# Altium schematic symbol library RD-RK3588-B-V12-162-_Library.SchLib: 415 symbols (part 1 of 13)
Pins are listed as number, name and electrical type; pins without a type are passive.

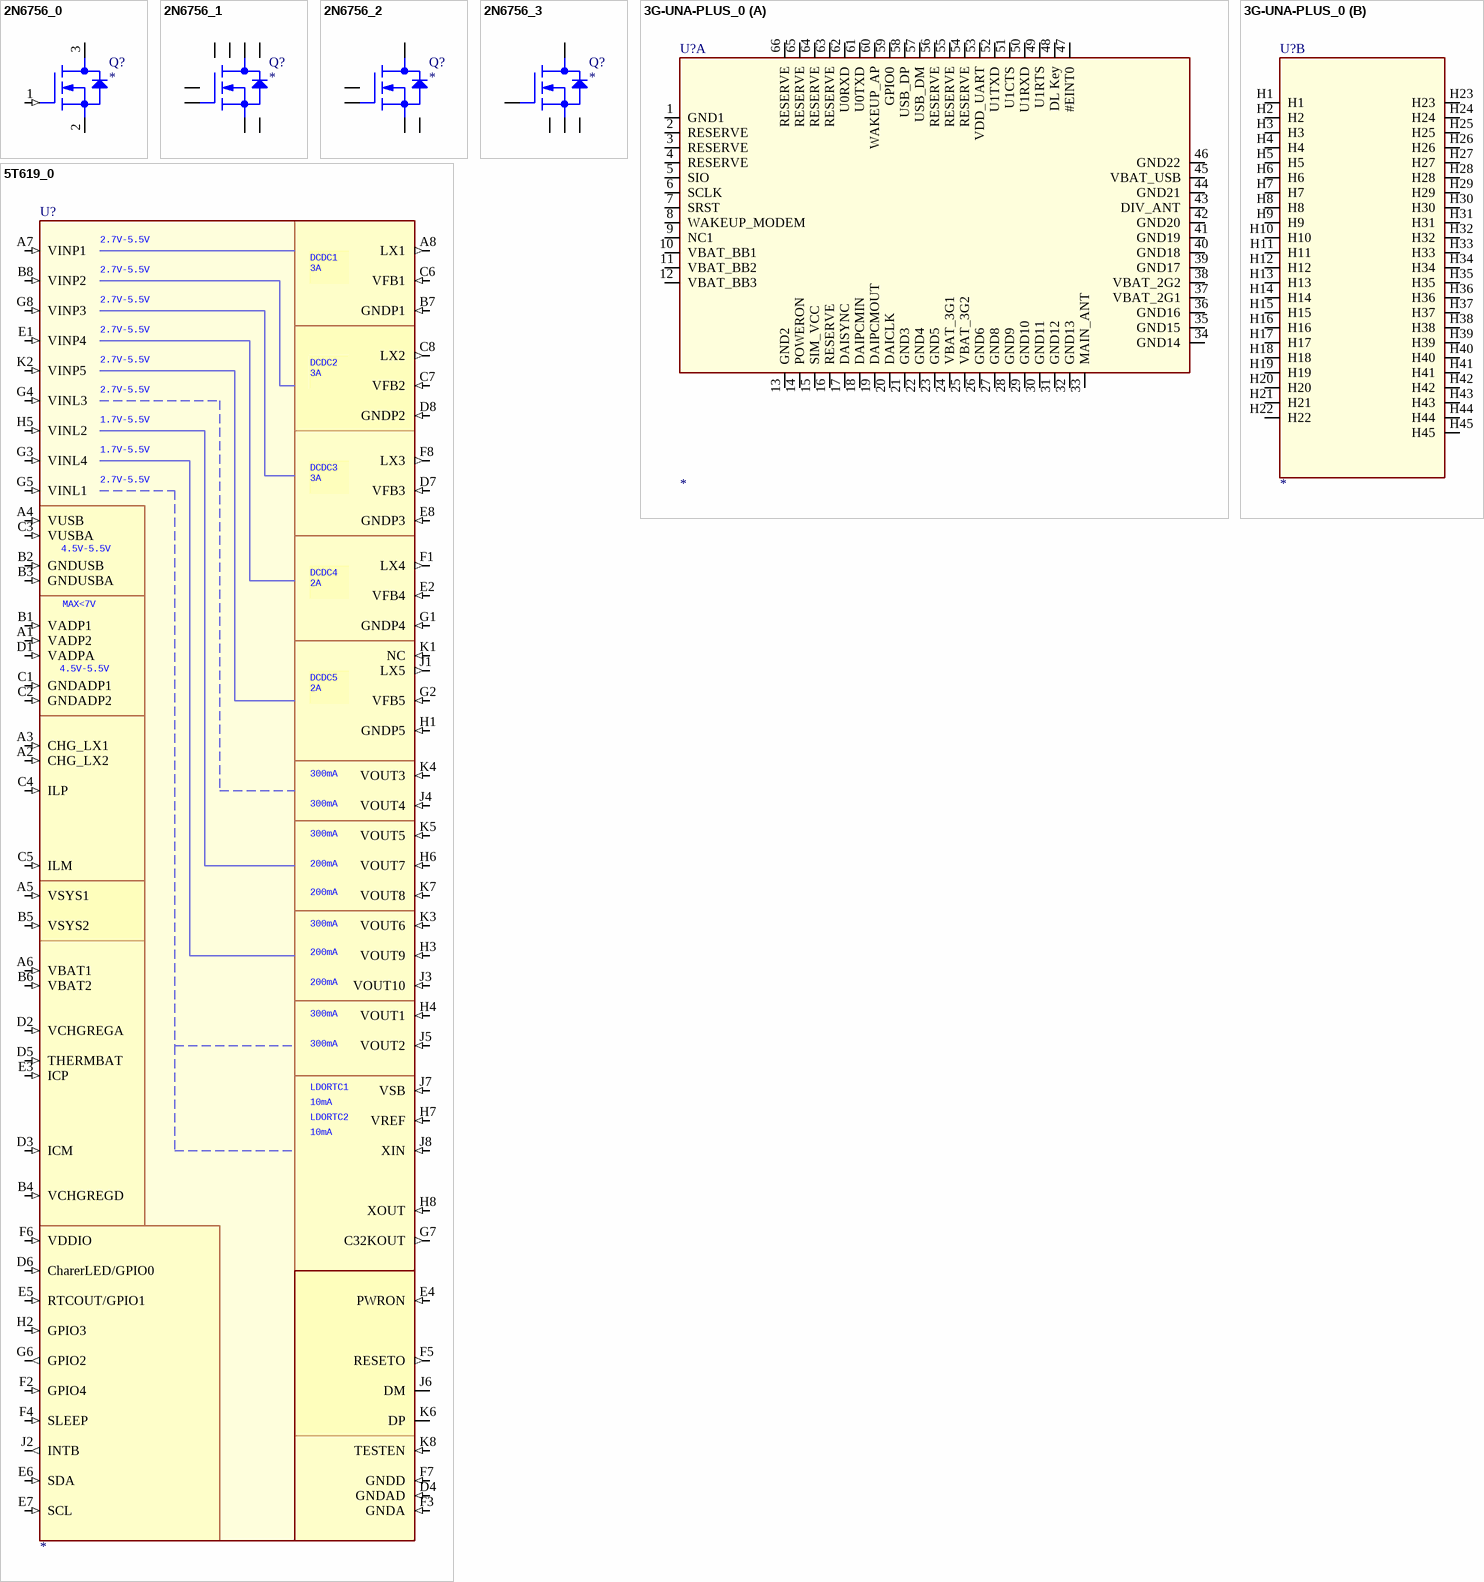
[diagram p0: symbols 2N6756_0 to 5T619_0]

## 2N6756_0
designator Q?
pins: 1 GATE (in), 2 SOURCE, 3 DRAIN

## 2N6756_1
designator Q?
pins: D1, D2, D3, D4, G1, G2, S1, S2

## 2N6756_2
designator Q?
pins: D1, G1, G2, S1, S2

## 2N6756_3
designator Q?
pins: D1, G1, G2, S1, S2

## 3G-UNA-PLUS_0
designator U?
part A pins: 1 GND1, 2 RESERVE, 3 RESERVE, 4 RESERVE, 5 SIO, 6 SCLK, 7 SRST, 8 WAKEUP_MODEM, 9 NC1, 10 VBAT_BB1, 11 VBAT_BB2, 12 VBAT_BB3, 13 GND2, 14 POWERON, 15 SIM_VCC, 16 RESERVE, 17 DAISYNC, 18 DAIPCMIN, 19 DAIPCMOUT, 20 DAICLK, 21 GND3, 22 GND4, 23 GND5, 24 VBAT_3G1, 25 VBAT_3G2, 26 GND6, 27 GND8, 28 GND9, 29 GND10, 30 GND11, 31 GND12, 32 GND13, 33 MAIN_ANT, 34 GND14, 35 GND15, 36 GND16, 37 VBAT_2G1, 38 VBAT_2G2, 39 GND17, 40 GND18, 41 GND19, 42 GND20, 43 DIV_ANT, 44 GND21, 45 VBAT_USB, 46 GND22, 47 #EINT0, 48 DL Key, 49 U1RTS, 50 U1RXD, 51 U1CTS, 52 U1TXD, 53 VDD_UART, 54 RESERVE, 55 RESERVE, 56 RESERVE, 57 USB_DM, 58 USB_DP, 59 GPIO0, 60 WAKEUP_AP, 61 U0TXD, 62 U0RXD, 63 RESERVE, 64 RESERVE, 65 RESERVE, 66 RESERVE
part B pins: H1, H2, H3, H4, H5, H6, H7, H8, H9, H10, H11, H12, H13, H14, H15, H16, H17, H18, H19, H20, H21, H22, H23, H24, H25, H26, H27, H28, H29, H30, H31, H32, H33, H34, H35, H36, H37, H38, H39, H40, H41, H42, H43, H44, H45

## 5T619_0
designator U?
pins: A1 VADP2 (in), A2 CHG_LX2 (in), A3 CHG_LX1 (in), A4 VUSB (in), A5 VSYS1 (in), A6 VBAT1 (in), A7 VINP1 (in), A8 LX1 (out), B1 VADP1 (in), B2 GNDUSB (in), B3 GNDUSBA (in), B4 VCHGREGD (in), B5 VSYS2 (in), B6 VBAT2 (in), B7 GNDP1 (in), B8 VINP2 (in), C1 GNDADP1 (in), C2 GNDADP2 (in), C3 VUSBA (in), C4 ILP (in), C5 ILM (in), C6 VFB1 (in), C7 VFB2 (in), C8 LX2 (out), D1 VADPA (in), D2 VCHGREGA (in), D3 ICM (in), D4 GNDAD (in), D5 THERMBAT (in), D6 CharerLED/GPIO0 (in), D7 VFB3 (in), D8 GNDP2 (in), E1 VINP4 (in), E2 VFB4 (in), E3 ICP (in), E4 PWRON (in), E5 RTCOUT/GPIO1 (in), E6 SDA (in), E7 SCL (in), E8 GNDP3 (in), F1 LX4 (out), F2 GPIO4 (in), F3 GNDA (in), F4 SLEEP (in), F5 RESETO (out), F6 VDDIO (in), F7 GNDD (in), F8 LX3 (out), G1 GNDP4 (in), G2 VFB5 (in), G3 VINL4 (in), G4 VINL3 (in), G5 VINL1 (in), G6 GPIO2 (out), G7 C32KOUT (out), G8 VINP3 (in), H1 GNDP5 (in), H2 GPIO3 (in), H3 VOUT9 (in), H4 VOUT1 (in), H5 VINL2 (in), H6 VOUT7 (in), H7 VREF (in), H8 XOUT (in), J1 LX5 (out), J2 INTB (out), J3 VOUT10 (in), J4 VOUT4 (in), J5 VOUT2 (in), J6 DM, J7 VSB (in), J8 XIN (in), K1 NC (in), K2 VINP5 (in), K3 VOUT6 (in), K4 VOUT3 (in), K5 VOUT5 (in), K6 DP, K7 VOUT8 (in), K8 TESTEN (in)

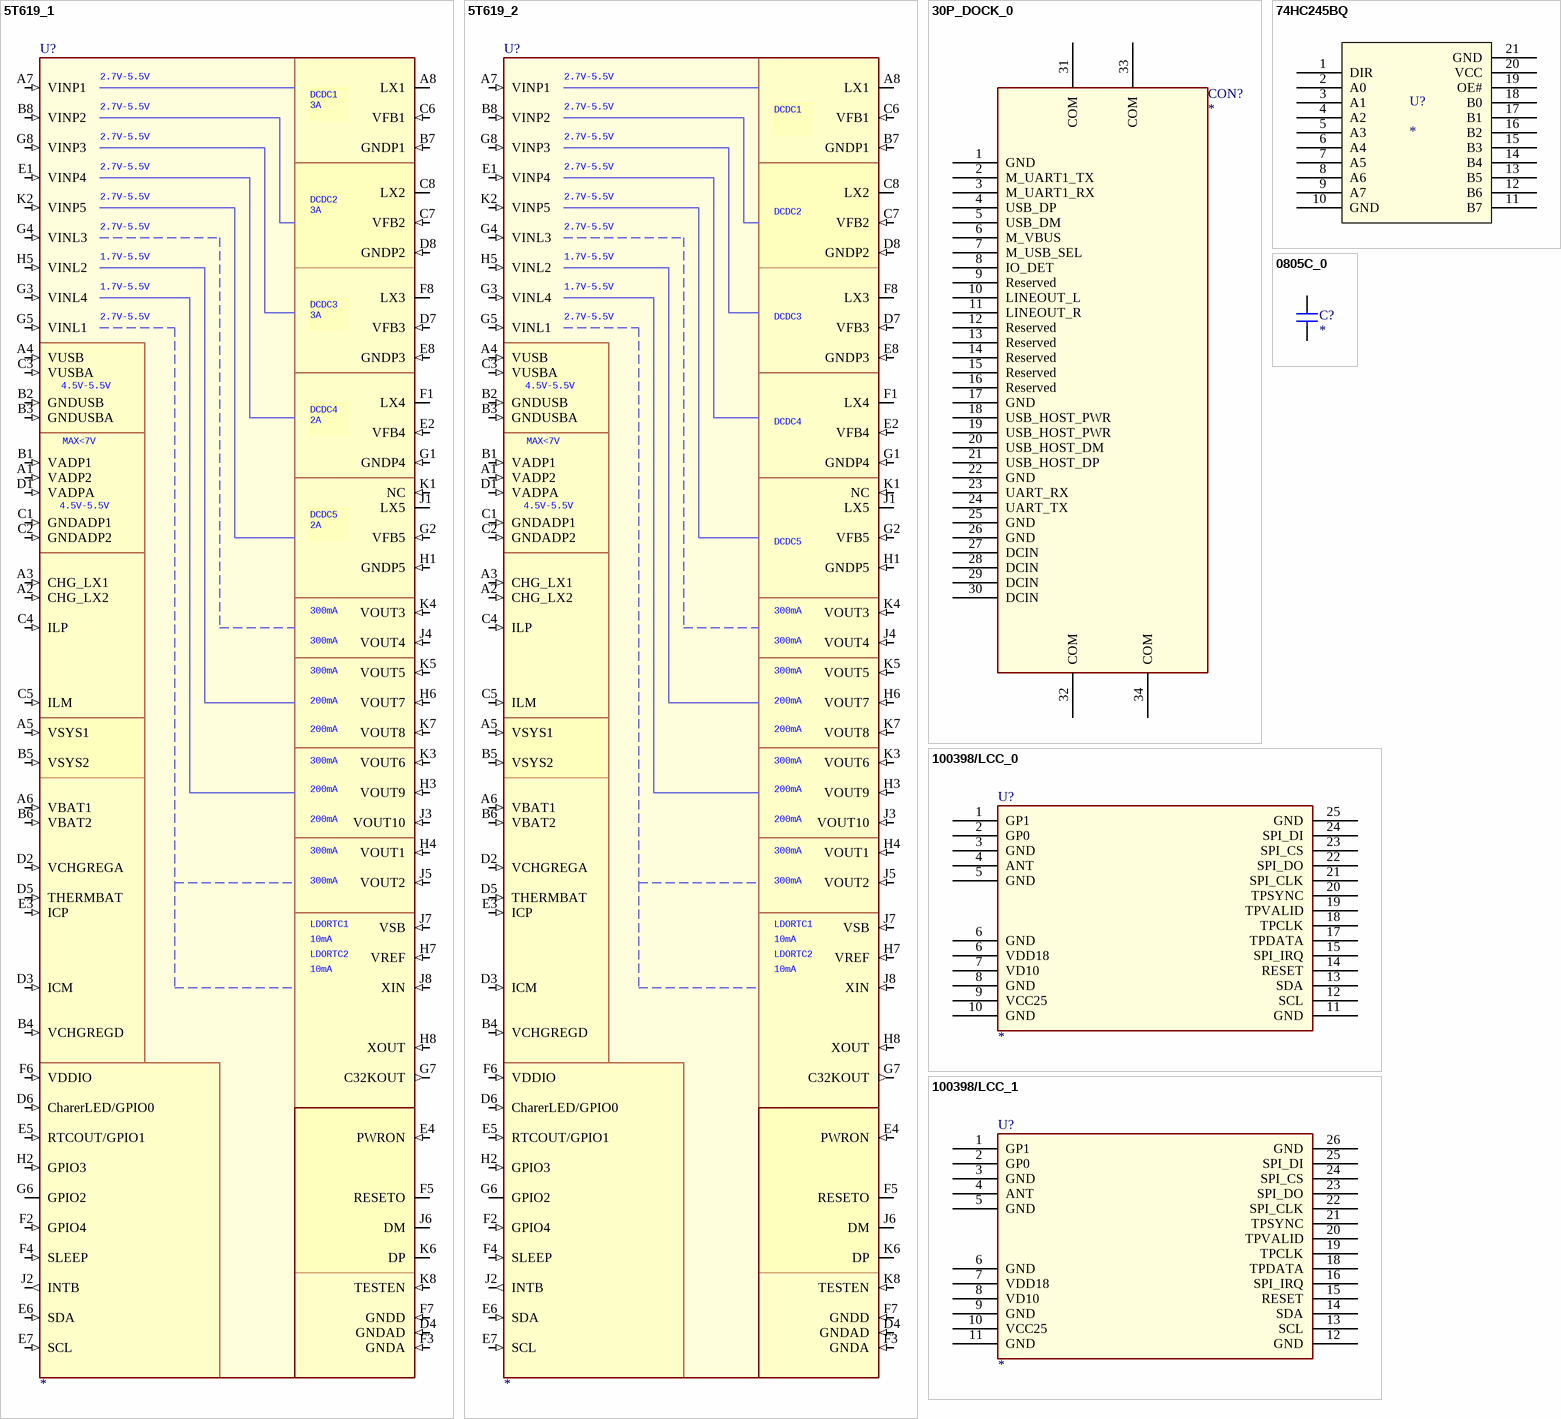
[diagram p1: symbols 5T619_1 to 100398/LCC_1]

## 5T619_1
designator U?
pins: A1 VADP2 (in), A2 CHG_LX2 (in), A3 CHG_LX1 (in), A4 VUSB (in), A5 VSYS1 (in), A6 VBAT1 (in), A7 VINP1 (in), A8 LX1, B1 VADP1 (in), B2 GNDUSB (in), B3 GNDUSBA (in), B4 VCHGREGD (in), B5 VSYS2 (in), B6 VBAT2 (in), B7 GNDP1 (in), B8 VINP2 (in), C1 GNDADP1 (in), C2 GNDADP2 (in), C3 VUSBA (in), C4 ILP (in), C5 ILM (in), C6 VFB1 (in), C7 VFB2 (in), C8 LX2, D1 VADPA (in), D2 VCHGREGA (in), D3 ICM (in), D4 GNDAD (in), D5 THERMBAT (in), D6 CharerLED/GPIO0 (in), D7 VFB3 (in), D8 GNDP2 (in), E1 VINP4 (in), E2 VFB4 (in), E3 ICP (in), E4 PWRON (in), E5 RTCOUT/GPIO1 (in), E6 SDA (in), E7 SCL (in), E8 GNDP3 (in), F1 LX4, F2 GPIO4 (in), F3 GNDA (in), F4 SLEEP (in), F5 RESETO, F6 VDDIO (in), F7 GNDD (in), F8 LX3, G1 GNDP4 (in), G2 VFB5 (in), G3 VINL4 (in), G4 VINL3 (in), G5 VINL1 (in), G6 GPIO2, G7 C32KOUT (out), G8 VINP3 (in), H1 GNDP5 (in), H2 GPIO3 (in), H3 VOUT9 (in), H4 VOUT1 (in), H5 VINL2 (in), H6 VOUT7 (in), H7 VREF (in), H8 XOUT (in), J1 LX5, J2 INTB (out), J3 VOUT10 (in), J4 VOUT4 (in), J5 VOUT2 (in), J6 DM, J7 VSB (in), J8 XIN (in), K1 NC (in), K2 VINP5 (in), K3 VOUT6 (in), K4 VOUT3 (in), K5 VOUT5 (in), K6 DP, K7 VOUT8 (in), K8 TESTEN (in)

## 5T619_2
designator U?
pins: A1 VADP2 (in), A2 CHG_LX2 (in), A3 CHG_LX1 (in), A4 VUSB (in), A5 VSYS1 (in), A6 VBAT1 (in), A7 VINP1 (in), A8 LX1, B1 VADP1 (in), B2 GNDUSB (in), B3 GNDUSBA (in), B4 VCHGREGD (in), B5 VSYS2 (in), B6 VBAT2 (in), B7 GNDP1 (in), B8 VINP2 (in), C1 GNDADP1 (in), C2 GNDADP2 (in), C3 VUSBA (in), C4 ILP (in), C5 ILM (in), C6 VFB1 (in), C7 VFB2 (in), C8 LX2, D1 VADPA (in), D2 VCHGREGA (in), D3 ICM (in), D4 GNDAD (in), D5 THERMBAT (in), D6 CharerLED/GPIO0 (in), D7 VFB3 (in), D8 GNDP2 (in), E1 VINP4 (in), E2 VFB4 (in), E3 ICP (in), E4 PWRON (in), E5 RTCOUT/GPIO1 (in), E6 SDA (in), E7 SCL (in), E8 GNDP3 (in), F1 LX4, F2 GPIO4 (in), F3 GNDA (in), F4 SLEEP (in), F5 RESETO, F6 VDDIO (in), F7 GNDD (in), F8 LX3, G1 GNDP4 (in), G2 VFB5 (in), G3 VINL4 (in), G4 VINL3 (in), G5 VINL1 (in), G6 GPIO2, G7 C32KOUT (out), G8 VINP3 (in), H1 GNDP5 (in), H2 GPIO3 (in), H3 VOUT9 (in), H4 VOUT1 (in), H5 VINL2 (in), H6 VOUT7 (in), H7 VREF (in), H8 XOUT (in), J1 LX5, J2 INTB (out), J3 VOUT10 (in), J4 VOUT4 (in), J5 VOUT2 (in), J6 DM, J7 VSB (in), J8 XIN (in), K1 NC (in), K2 VINP5 (in), K3 VOUT6 (in), K4 VOUT3 (in), K5 VOUT5 (in), K6 DP, K7 VOUT8 (in), K8 TESTEN (in)

## 30P_DOCK_0
designator CON?
footprint 30P_DOCK_1
pins: 1 GND, 2 M_UART1_TX, 3 M_UART1_RX, 4 USB_DP, 5 USB_DM, 6 M_VBUS, 7 M_USB_SEL, 8 IO_DET, 9 Reserved, 10 LINEOUT_L, 11 LINEOUT_R, 12 Reserved, 13 Reserved, 14 Reserved, 15 Reserved, 16 Reserved, 17 GND, 18 USB_HOST_PWR, 19 USB_HOST_PWR, 20 USB_HOST_DM, 21 USB_HOST_DP, 22 GND, 23 UART_RX, 24 UART_TX, 25 GND, 26 GND, 27 DCIN, 28 DCIN, 29 DCIN, 30 DCIN, 31 COM, 32 COM, 33 COM, 34 COM

## 74HC245BQ
designator U?
pins: 1 DIR, 2 A0, 3 A1, 4 A2, 5 A3, 6 A4, 7 A5, 8 A6, 9 A7, 10 GND, 11 B7, 12 B6, 13 B5, 14 B4, 15 B3, 16 B2, 17 B1, 18 B0, 19 OE#, 20 VCC, 21 GND

## 0805C_0
designator C?
footprint 0805C
pins: 1, 2

## 100398/LCC_0
designator U?
pins: 1 GP1, 2 GP0, 3 GND, 4 ANT, 5 GND, 6 VDD18, 6 GND, 7 VD10, 8 GND, 9 VCC25, 10 GND, 11 GND, 12 SCL, 13 SDA, 14 RESET, 15 SPI_IRQ, 17 TPDATA, 18 TPCLK, 19 TPVALID, 20 TPSYNC, 21 SPI_CLK, 22 SPI_DO, 23 SPI_CS, 24 SPI_DI, 25 GND

## 100398/LCC_1
designator U?
pins: 1 GP1, 2 GP0, 3 GND, 4 ANT, 5 GND, 6 GND, 7 VDD18, 8 VD10, 9 GND, 10 VCC25, 11 GND, 12 GND, 13 SCL, 14 SDA, 15 RESET, 16 SPI_IRQ, 18 TPDATA, 19 TPCLK, 20 TPVALID, 21 TPSYNC, 22 SPI_CLK, 23 SPI_DO, 24 SPI_CS, 25 SPI_DI, 26 GND

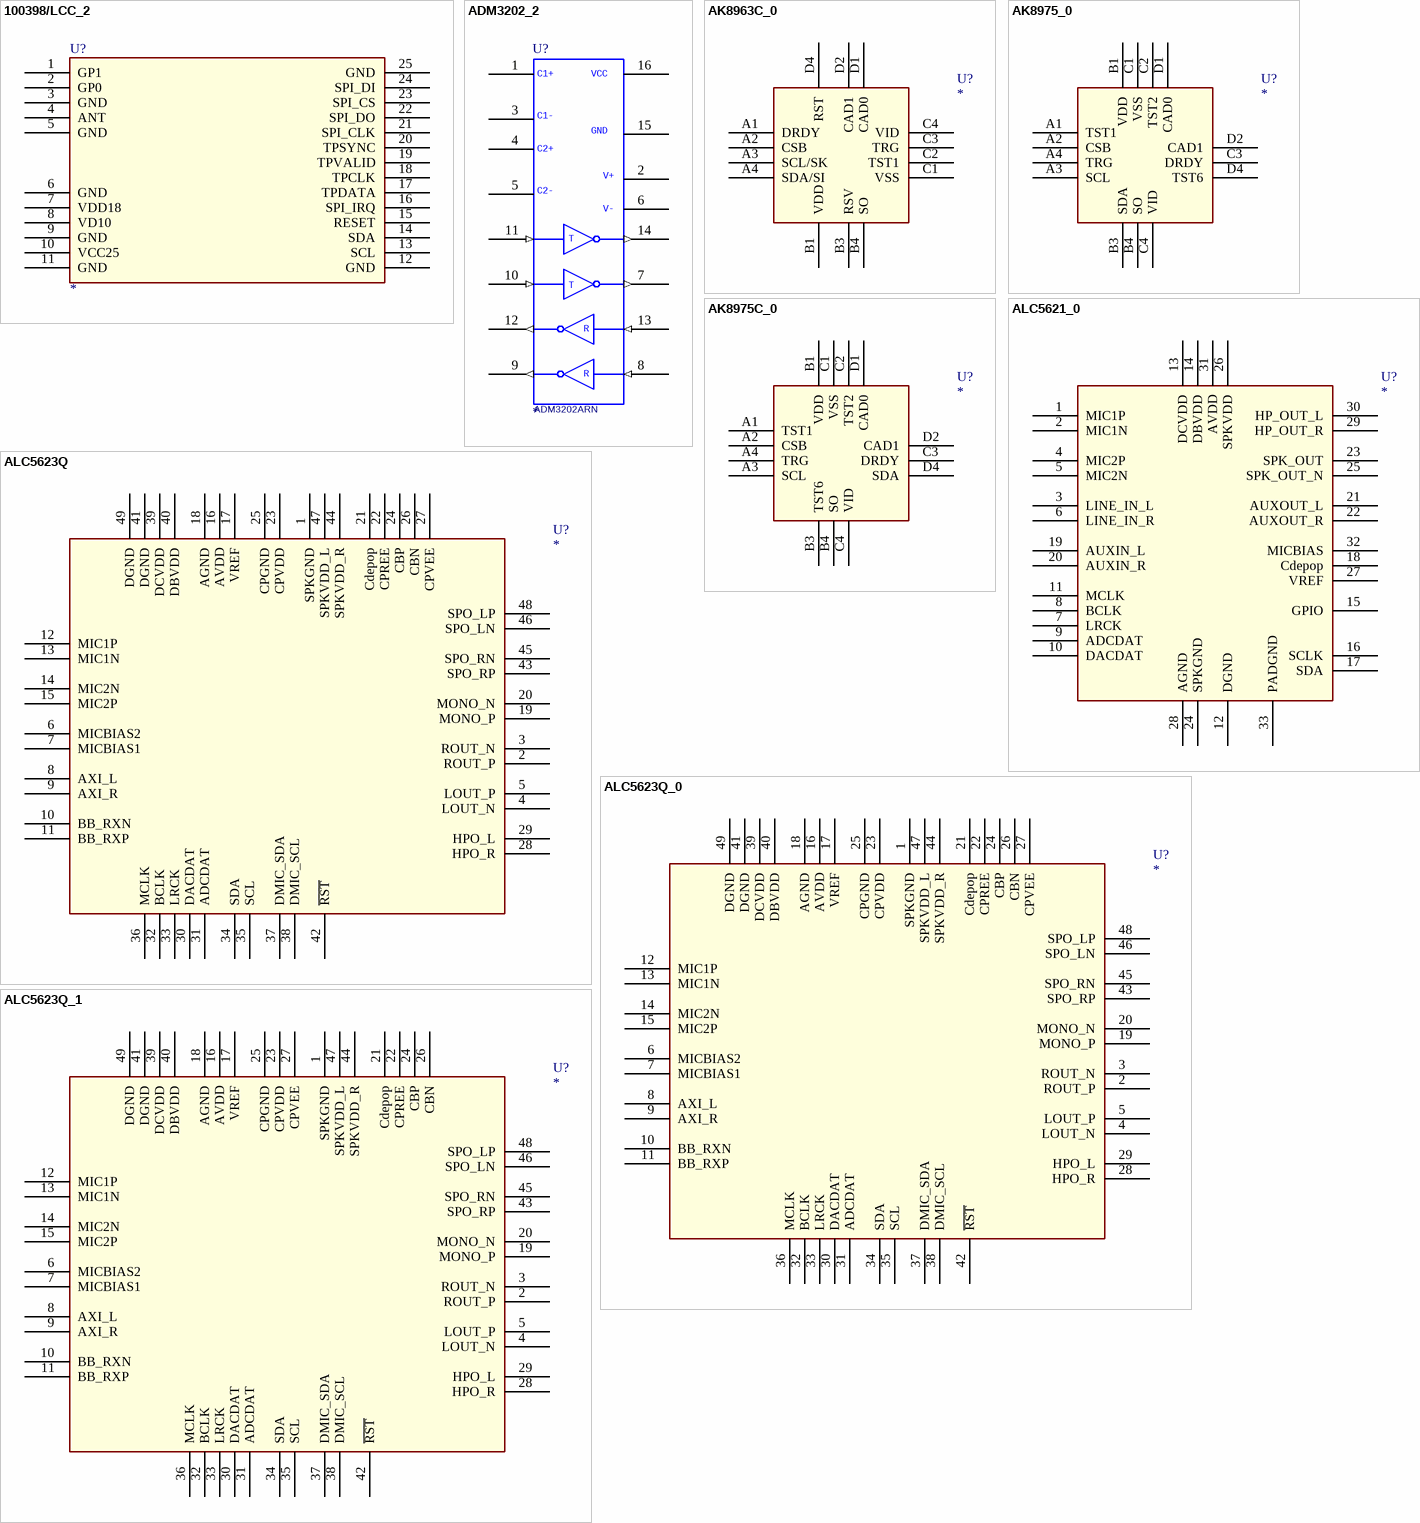
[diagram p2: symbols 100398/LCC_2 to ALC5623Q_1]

## 100398/LCC_2
designator U?
pins: 1 GP1, 2 GP0, 3 GND, 4 ANT, 5 GND, 6 GND, 7 VDD18, 8 VD10, 9 GND, 10 VCC25, 11 GND, 12 GND, 13 SCL, 14 SDA, 15 RESET, 16 SPI_IRQ, 17 TPDATA, 18 TPCLK, 19 TPVALID, 20 TPSYNC, 21 SPI_CLK, 22 SPI_DO, 23 SPI_CS, 24 SPI_DI, 25 GND

## ADM3202_2
designator U?  VAL: ADM3202ARN
FAB: AD; DEV: SO16; REF: 3
pins: 1, 2 V+, 3, 4, 5, 6 V-, 7 (out), 8 (in), 9 (out), 10 (in), 11 (in), 12 (out), 13 (in), 14 (out), 15 GND (power), 16 VCC (power)

## AK8963C_0
designator U?
footprint AK8975B
pins: A1 DRDY, A2 CSB, A3 SCL/SK, A4 SDA/SI, B1 VDD, B3 RSV, B4 SO, C1 VSS, C2 TST1, C3 TRG, C4 VID, D1 CAD0, D2 CAD1, D4 RST

## AK8975_0
designator U?
footprint QFN16-4X4
pins: A1 TST1, A2 CSB, A3 SCL, A4 TRG, B1 VDD, B3 SDA, B4 SO, C1 VSS, C2 TST2, C3 DRDY, C4 VID, D1 CAD0, D2 CAD1, D4 TST6

## AK8975C_0
designator U?
footprint AK8975B
pins: A1 TST1, A2 CSB, A3 SCL, A4 TRG, B1 VDD, B3 TST6, B4 SO, C1 VSS, C2 TST2, C3 DRDY, C4 VID, D1 CAD0, D2 CAD1, D4 SDA

## ALC5621_0
designator U?
footprint QFN32
pins: 1 MIC1P, 2 MIC1N, 3 LINE_IN_L, 4 MIC2P, 5 MIC2N, 6 LINE_IN_R, 7 LRCK, 8 BCLK, 9 ADCDAT, 10 DACDAT, 11 MCLK, 12 DGND, 13 DCVDD, 14 DBVDD, 15 GPIO, 16 SCLK, 17 SDA, 18 Cdepop, 19 AUXIN_L, 20 AUXIN_R, 21 AUXOUT_L, 22 AUXOUT_R, 23 SPK_OUT, 24 SPKGND, 25 SPK_OUT_N, 26 SPKVDD, 27 VREF, 28 AGND, 29 HP_OUT_R, 30 HP_OUT_L, 31 AVDD, 32 MICBIAS, 33 PADGND

## ALC5623Q
designator U?
footprint QFN48-6X6
pins: 1 SPKGND, 2 ROUT_P, 3 ROUT_N, 4 LOUT_N, 5 LOUT_P, 6 MICBIAS2, 7 MICBIAS1, 8 AXI_L, 9 AXI_R, 10 BB_RXN, 11 BB_RXP, 12 MIC1P, 13 MIC1N, 14 MIC2N, 15 MIC2P, 16 AVDD, 17 VREF, 18 AGND, 19 MONO_P, 20 MONO_N, 21 Cdepop, 22 CPREE, 23 CPVDD, 24 CBP, 25 CPGND, 26 CBN, 27 CPVEE, 28 HPO_R, 29 HPO_L, 30 DACDAT, 31 ADCDAT, 32 BCLK, 33 LRCK, 34 SDA, 35 SCL, 36 MCLK, 37 DMIC_SDA, 38 DMIC_SCL, 39 DCVDD, 40 DBVDD, 41 DGND, 42 ~{RST}, 43 SPO_RP, 44 SPKVDD_R, 45 SPO_RN, 46 SPO_LN, 47 SPKVDD_L, 48 SPO_LP, 49 DGND

## ALC5623Q_0
designator U?
footprint QFN48-6X6
pins: 1 SPKGND, 2 ROUT_P, 3 ROUT_N, 4 LOUT_N, 5 LOUT_P, 6 MICBIAS2, 7 MICBIAS1, 8 AXI_L, 9 AXI_R, 10 BB_RXN, 11 BB_RXP, 12 MIC1P, 13 MIC1N, 14 MIC2N, 15 MIC2P, 16 AVDD, 17 VREF, 18 AGND, 19 MONO_P, 20 MONO_N, 21 Cdepop, 22 CPREE, 23 CPVDD, 24 CBP, 25 CPGND, 26 CBN, 27 CPVEE, 28 HPO_R, 29 HPO_L, 30 DACDAT, 31 ADCDAT, 32 BCLK, 33 LRCK, 34 SDA, 35 SCL, 36 MCLK, 37 DMIC_SDA, 38 DMIC_SCL, 39 DCVDD, 40 DBVDD, 41 DGND, 42 ~{RST}, 43 SPO_RP, 44 SPKVDD_R, 45 SPO_RN, 46 SPO_LN, 47 SPKVDD_L, 48 SPO_LP, 49 DGND

## ALC5623Q_1
designator U?
footprint QFN48-6X6
pins: 1 SPKGND, 2 ROUT_P, 3 ROUT_N, 4 LOUT_N, 5 LOUT_P, 6 MICBIAS2, 7 MICBIAS1, 8 AXI_L, 9 AXI_R, 10 BB_RXN, 11 BB_RXP, 12 MIC1P, 13 MIC1N, 14 MIC2N, 15 MIC2P, 16 AVDD, 17 VREF, 18 AGND, 19 MONO_P, 20 MONO_N, 21 Cdepop, 22 CPREE, 23 CPVDD, 24 CBP, 25 CPGND, 26 CBN, 27 CPVEE, 28 HPO_R, 29 HPO_L, 30 DACDAT, 31 ADCDAT, 32 BCLK, 33 LRCK, 34 SDA, 35 SCL, 36 MCLK, 37 DMIC_SDA, 38 DMIC_SCL, 39 DCVDD, 40 DBVDD, 41 DGND, 42 ~{RST}, 43 SPO_RP, 44 SPKVDD_R, 45 SPO_RN, 46 SPO_LN, 47 SPKVDD_L, 48 SPO_LP, 49 DGND

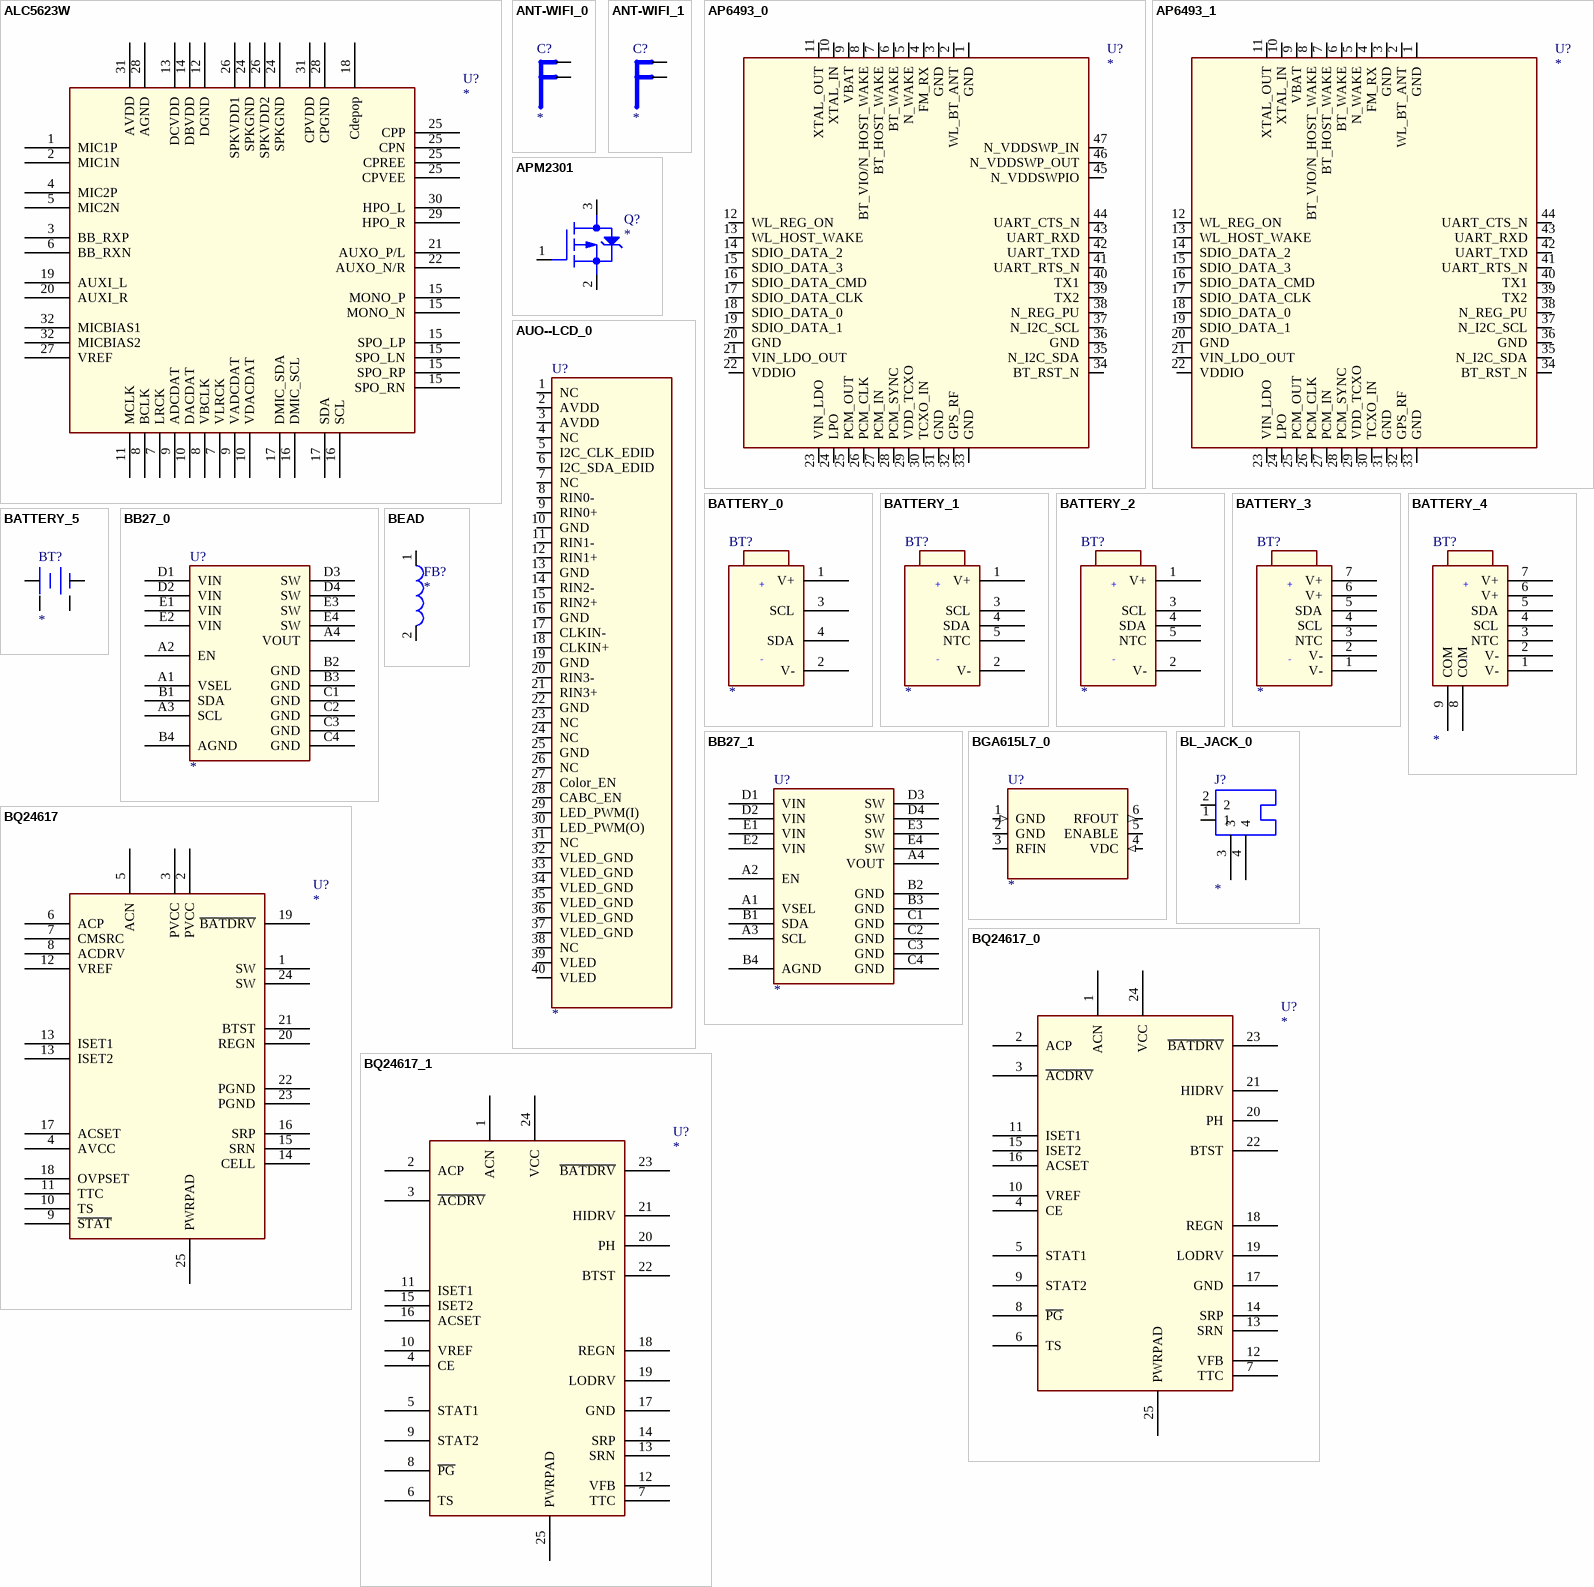
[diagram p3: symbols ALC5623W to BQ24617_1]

## ALC5623W
designator U?
footprint GBA49
pins: 1 MIC1P, 2 MIC1N, 3 BB_RXP, 4 MIC2P, 5 MIC2N, 6 BB_RXN, 7 LRCK, 7 VLRCK, 8 BCLK, 8 VBCLK, 9 ADCDAT, 9 VADCDAT, 10 DACDAT, 10 VDACDAT, 11 MCLK, 12 DGND, 13 DCVDD, 14 DBVDD, 15 SPO_RN, 15 SPO_RP, 15 SPO_LP, 15 SPO_LN, 15 MONO_P, 15 MONO_N, 16 SCL, 16 DMIC_SCL, 17 SDA, 17 DMIC_SDA, 18 Cdepop, 19 AUXI_L, 20 AUXI_R, 21 AUXO_P/L, 22 AUXO_N/R, 24 SPKGND, 24 SPKGND, 25 CPVEE, 25 CPREE, 25 CPN, 25 CPP, 26 SPKVDD1, 26 SPKVDD2, 27 VREF, 28 AGND, 28 CPGND, 29 HPO_R, 30 HPO_L, 31 AVDD, 31 CPVDD, 32 MICBIAS1, 32 MICBIAS2

## ANT-WIFI_0
designator C?
pins: 1, 2

## ANT-WIFI_1
designator C?
pins: 1, 2

## AP6493_0
designator U?
pins: 1 GND (power), 2 WL_BT_ANT, 3 GND (power), 4 FM_RX, 5 N_WAKE, 6 BT_WAKE, 7 BT_HOST_WAKE, 8 BT_VIO/N_HOST_WAKE, 9 VBAT, 10 XTAL_IN, 11 XTAL_OUT, 12 WL_REG_ON, 13 WL_HOST_WAKE, 14 SDIO_DATA_2, 15 SDIO_DATA_3, 16 SDIO_DATA_CMD, 17 SDIO_DATA_CLK, 18 SDIO_DATA_0, 19 SDIO_DATA_1, 20 GND (power), 21 VIN_LDO_OUT, 22 VDDIO, 23 VIN_LDO, 24 LPO, 25 PCM_OUT, 26 PCM_CLK, 27 PCM_IN, 28 PCM_SYNC, 29 VDD_TCXO, 30 TCXO_IN, 31 GND (power), 32 GPS_RF, 33 GND (power), 34 BT_RST_N, 35 N_I2C_SDA, 36 GND (power), 37 N_I2C_SCL, 38 N_REG_PU, 39 TX2, 40 TX1, 41 UART_RTS_N, 42 UART_TXD, 43 UART_RXD, 44 UART_CTS_N, 45 N_VDDSWPIO, 46 N_VDDSWP_OUT, 47 N_VDDSWP_IN

## AP6493_1
designator U?
pins: 1 GND (power), 2 WL_BT_ANT, 3 GND (power), 4 FM_RX, 5 N_WAKE, 6 BT_WAKE, 7 BT_HOST_WAKE, 8 BT_VIO/N_HOST_WAKE, 9 VBAT, 10 XTAL_IN, 11 XTAL_OUT, 12 WL_REG_ON, 13 WL_HOST_WAKE, 14 SDIO_DATA_2, 15 SDIO_DATA_3, 16 SDIO_DATA_CMD, 17 SDIO_DATA_CLK, 18 SDIO_DATA_0, 19 SDIO_DATA_1, 20 GND (power), 21 VIN_LDO_OUT, 22 VDDIO, 23 VIN_LDO, 24 LPO, 25 PCM_OUT, 26 PCM_CLK, 27 PCM_IN, 28 PCM_SYNC, 29 VDD_TCXO, 30 TCXO_IN, 31 GND (power), 32 GPS_RF, 33 GND (power), 34 BT_RST_N, 35 N_I2C_SDA, 36 GND (power), 37 N_I2C_SCL, 38 N_REG_PU, 39 TX2, 40 TX1, 41 UART_RTS_N, 42 UART_TXD, 43 UART_RXD, 44 UART_CTS_N

## APM2301
designator Q?
pins: 1 G, 2 S, 3 D

## AUO--LCD_0
designator U?
pins: 1 NC, 2 AVDD, 3 AVDD, 4 NC, 5 I2C_CLK_EDID, 6 I2C_SDA_EDID, 7 NC, 8 RIN0-, 9 RIN0+, 10 GND, 11 RIN1-, 12 RIN1+, 13 GND, 14 RIN2-, 15 RIN2+, 16 GND, 17 CLKIN-, 18 CLKIN+, 19 GND, 20 RIN3-, 21 RIN3+, 22 GND, 23 NC, 24 NC, 25 GND, 26 NC, 27 Color_EN, 28 CABC_EN, 29 LED_PWM(I), 30 LED_PWM(O), 31 NC, 32 VLED_GND, 33 VLED_GND, 34 VLED_GND, 35 VLED_GND, 36 VLED_GND, 37 VLED_GND, 38 NC, 39 VLED, 40 VLED

## BATTERY_0
designator BT?
pins: 1 V+, 2 V-, 3 SCL, 4 SDA

## BATTERY_1
designator BT?
pins: 1 V+, 2 V-, 3 SCL, 4 SDA, 5 NTC

## BATTERY_2
designator BT?
pins: 1 V+, 2 V-, 3 SCL, 4 SDA, 5 NTC

## BATTERY_3
designator BT?
pins: 1 V-, 2 V-, 3 NTC, 4 SCL, 5 SDA, 6 V+, 7 V+

## BATTERY_4
designator BT?
pins: 1 V- (power), 2 V- (power), 3 NTC, 4 SCL, 5 SDA, 6 V+ (power), 7 V+ (power), 8 COM, 9 COM

## BATTERY_5
designator BT?
pins: 1 +, 2 -, 3, 4

## BB27_0
designator U?
footprint WLCSP-20
pins: A1 VSEL, A2 EN, A3 SCL, A4 VOUT, B1 SDA, B2 GND (power), B3 GND (power), B4 AGND, C1 GND (power), C2 GND (power), C3 GND (power), C4 GND (power), D1 VIN (power), D2 VIN (power), D3 SW (power), D4 SW (power), E1 VIN (power), E2 VIN (power), E3 SW (power), E4 SW (power)

## BB27_1
designator U?
footprint WLCSP-20
pins: A1 VSEL, A2 EN, A3 SCL, A4 VOUT, B1 SDA, B2 GND (power), B3 GND (power), B4 AGND, C1 GND (power), C2 GND (power), C3 GND (power), C4 GND (power), D1 VIN (power), D2 VIN (power), D3 SW (power), D4 SW (power), E1 VIN (power), E2 VIN (power), E3 SW (power), E4 SW (power)

## BEAD
designator FB?
pins: 1, 2

## BGA615L7_0
designator U?
footprint P-TSLP-7-1
pins: 1 GND (in), 2 GND, 3 RFIN (power), 4 VDC (in), 5 ENABLE (power), 6 RFOUT (out)

## BL_JACK_0
designator J?
pins: 1, 2, 3, 4

## BQ24617
designator U?
footprint QFN24
pins: 1 SW, 2 PVCC, 3 PVCC, 4 AVCC, 5 ACN, 6 ACP, 7 CMSRC, 8 ACDRV, 9 ~{STAT}, 10 TS, 11 TTC, 12 VREF, 13 ISET1, 13 ISET2, 14 CELL, 15 SRN, 16 SRP, 17 ACSET, 18 OVPSET, 19 ~{BATDRV}, 20 REGN, 21 BTST, 22 PGND, 23 PGND, 24 SW, 25 PWRPAD

## BQ24617_0
designator U?
footprint QFN24
pins: 1 ACN, 2 ACP, 3 ~{ACDRV}, 4 CE, 5 STAT1, 6 TS, 7 TTC, 8 ~{PG}, 9 STAT2, 10 VREF, 11 ISET1, 12 VFB, 13 SRN, 14 SRP, 15 ISET2, 16 ACSET, 17 GND, 18 REGN, 19 LODRV, 20 PH, 21 HIDRV, 22 BTST, 23 ~{BATDRV}, 24 VCC, 25 PWRPAD

## BQ24617_1
designator U?
footprint QFN24
pins: 1 ACN, 2 ACP, 3 ~{ACDRV}, 4 CE, 5 STAT1, 6 TS, 7 TTC, 8 ~{PG}, 9 STAT2, 10 VREF, 11 ISET1, 12 VFB, 13 SRN, 14 SRP, 15 ISET2, 16 ACSET, 17 GND, 18 REGN, 19 LODRV, 20 PH, 21 HIDRV, 22 BTST, 23 ~{BATDRV}, 24 VCC, 25 PWRPAD

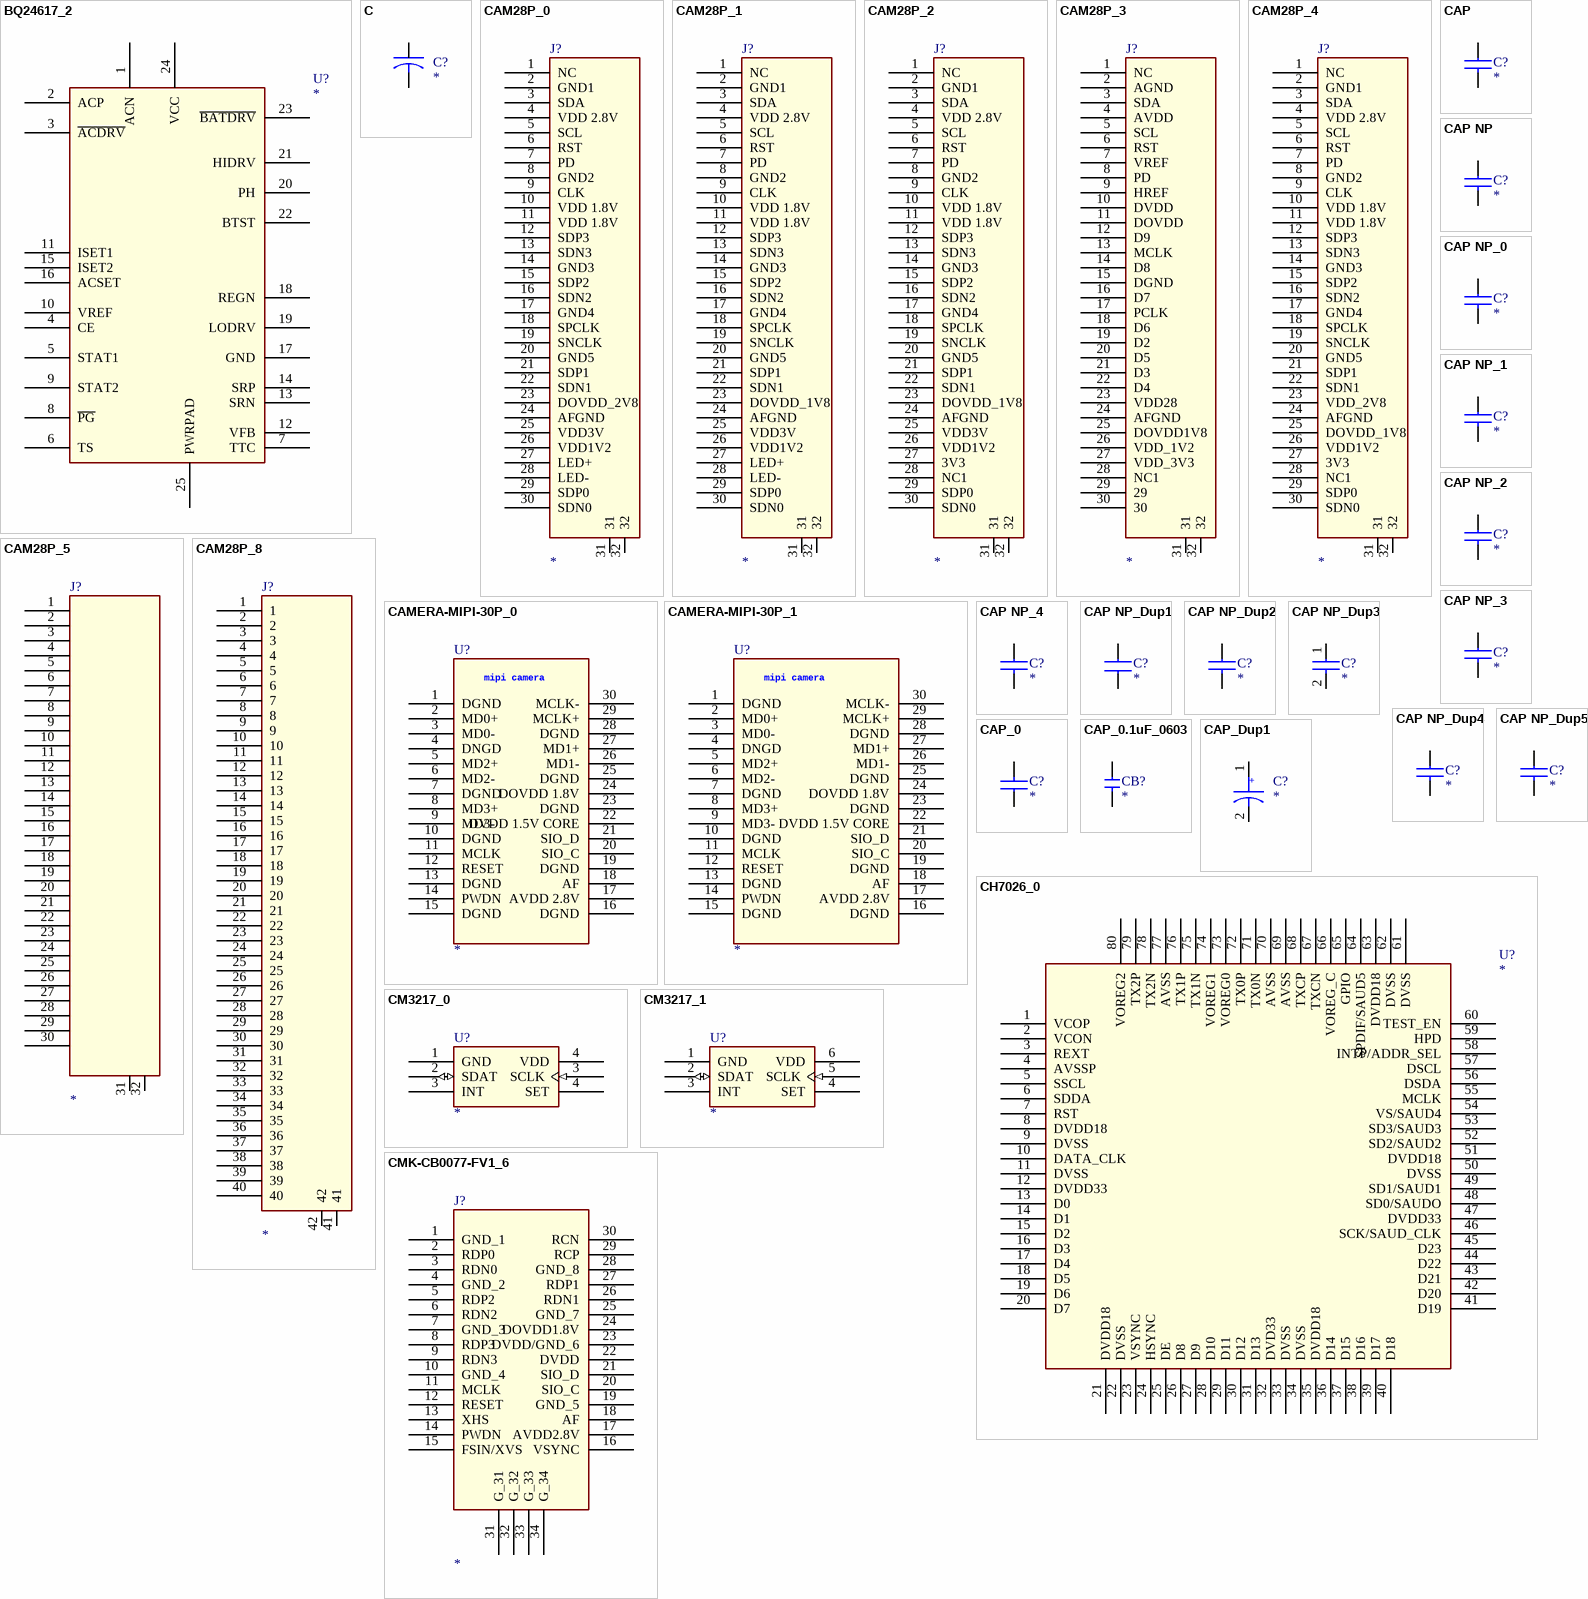
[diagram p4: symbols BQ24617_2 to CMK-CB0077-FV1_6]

## BQ24617_2
designator U?
footprint QFN24
pins: 1 ACN, 2 ACP, 3 ~{ACDRV}, 4 CE, 5 STAT1, 6 TS, 7 TTC, 8 ~{PG}, 9 STAT2, 10 VREF, 11 ISET1, 12 VFB, 13 SRN, 14 SRP, 15 ISET2, 16 ACSET, 17 GND, 18 REGN, 19 LODRV, 20 PH, 21 HIDRV, 22 BTST, 23 ~{BATDRV}, 24 VCC, 25 PWRPAD

## C
designator C?
pins: 1, 2

## CAM28P_0
designator J?
footprint FPC28_MICRO
pins: 1 NC, 2 GND1, 3 SDA, 4 VDD 2.8V (power), 5 SCL, 6 RST, 7 PD, 8 GND2, 9 CLK, 10 VDD 1.8V (power), 11 VDD 1.8V (power), 12 SDP3, 13 SDN3, 14 GND3, 15 SDP2, 16 SDN2, 17 GND4, 18 SPCLK, 19 SNCLK, 20 GND5, 21 SDP1, 22 SDN1, 23 DOVDD_2V8 (power), 24 AFGND, 25 VDD3V, 26 VDD1V2, 27 LED+, 28 LED-, 29 SDP0, 30 SDN0, 31, 32

## CAM28P_1
designator J?
footprint FPC28_MICRO
pins: 1 NC, 2 GND1, 3 SDA, 4 VDD 2.8V (power), 5 SCL, 6 RST, 7 PD, 8 GND2, 9 CLK, 10 VDD 1.8V (power), 11 VDD 1.8V (power), 12 SDP3, 13 SDN3, 14 GND3, 15 SDP2, 16 SDN2, 17 GND4, 18 SPCLK, 19 SNCLK, 20 GND5, 21 SDP1, 22 SDN1, 23 DOVDD_1V8 (power), 24 AFGND, 25 VDD3V, 26 VDD1V2, 27 LED+, 28 LED-, 29 SDP0, 30 SDN0, 31, 32

## CAM28P_2
designator J?
footprint FPC28_MICRO
pins: 1 NC, 2 GND1, 3 SDA, 4 VDD 2.8V (power), 5 SCL, 6 RST, 7 PD, 8 GND2, 9 CLK, 10 VDD 1.8V (power), 11 VDD 1.8V (power), 12 SDP3, 13 SDN3, 14 GND3, 15 SDP2, 16 SDN2, 17 GND4, 18 SPCLK, 19 SNCLK, 20 GND5, 21 SDP1, 22 SDN1, 23 DOVDD_1V8 (power), 24 AFGND, 25 VDD3V, 26 VDD1V2, 27 3V3, 28 NC1, 29 SDP0, 30 SDN0, 31, 32

## CAM28P_3
designator J?
footprint FPC28_MICRO
pins: 1 NC, 2 AGND, 3 SDA, 4 AVDD, 5 SCL, 6 RST, 7 VREF, 8 PD, 9 HREF, 10 DVDD, 11 DOVDD, 12 D9, 13 MCLK, 14 D8, 15 DGND, 16 D7, 17 PCLK, 18 D6, 19 D2, 20 D5, 21 D3, 22 D4, 23 VDD28, 24 AFGND, 25 DOVDD1V8, 26 VDD_1V2, 27 VDD_3V3, 28 NC1, 29, 30, 31, 32

## CAM28P_4
designator J?
footprint FPC28_MICRO
pins: 1 NC, 2 GND1, 3 SDA, 4 VDD 2.8V (power), 5 SCL, 6 RST, 7 PD, 8 GND2, 9 CLK, 10 VDD 1.8V (power), 11 VDD 1.8V (power), 12 SDP3, 13 SDN3, 14 GND3, 15 SDP2, 16 SDN2, 17 GND4, 18 SPCLK, 19 SNCLK, 20 GND5, 21 SDP1, 22 SDN1, 23 VDD_2V8 (power), 24 AFGND, 25 DOVDD_1V8, 26 VDD1V2, 27 3V3, 28 NC1, 29 SDP0, 30 SDN0, 31, 32

## CAM28P_5
designator J?
footprint FPC28_MICRO
pins: 1 NC, 2 GND1, 3 SDA, 4 VDD 2.8V (power), 5 SCL, 6 RST, 7 PD, 8 GND2, 9 CLK, 10 VDD 1.8V (power), 11 VDD 1.8V (power), 12 SDP3, 13 SDN3, 14 GND3, 15 SDP2, 16 SDN2, 17 GND4, 18 SPCLK, 19 SNCLK, 20 GND5, 21 SDP1, 22 SDN1, 23 VDD_2V8 (power), 24 AFGND, 25 DOVDD_1V8, 26 VDD1V2, 27 3V3, 28 NC1, 29 SDP0, 30 SDN0, 31, 32

## CAM28P_8
designator J?
footprint FPC28_MICRO
pins: 1, 2, 3, 4, 5, 6, 7, 8, 9, 10, 11, 12, 13, 14, 15, 16, 17, 18, 19, 20, 21, 22, 23, 24, 25, 26, 27, 28, 29, 30, 31, 32, 33, 34, 35, 36, 37, 38, 39, 40, 41, 42

## CAMERA-MIPI-30P_0
designator U?
pins: 1 DGND, 2 MD0+, 3 MD0-, 4 DNGD, 5 MD2+, 6 MD2-, 7 DGND, 8 MD3+, 9 MD3-, 10 DGND, 11 MCLK, 12 RESET, 13 DGND, 14 PWDN, 15 DGND, 16 DGND, 17 AVDD 2.8V, 18 AF, 19 DGND, 20 SIO_C, 21 SIO_D, 22 DVDD 1.5V CORE, 23 DGND, 24 DOVDD 1.8V, 25 DGND, 26 MD1-, 27 MD1+, 28 DGND, 29 MCLK+, 30 MCLK-

## CAMERA-MIPI-30P_1
designator U?
pins: 1 DGND, 2 MD0+, 3 MD0-, 4 DNGD, 5 MD2+, 6 MD2-, 7 DGND, 8 MD3+, 9 MD3-, 10 DGND, 11 MCLK, 12 RESET, 13 DGND, 14 PWDN, 15 DGND, 16 DGND, 17 AVDD 2.8V, 18 AF, 19 DGND, 20 SIO_C, 21 SIO_D, 22 DVDD 1.5V CORE, 23 DGND, 24 DOVDD 1.8V, 25 DGND, 26 MD1-, 27 MD1+, 28 DGND, 29 MCLK+, 30 MCLK-

## CAP
designator C?
pins: 1, 2

## CAP NP
designator C?
pins: 1, 2

## CAP NP_0
designator C?
pins: 1, 2

## CAP NP_1
designator C?
pins: 1, 2

## CAP NP_2
designator C?
pins: 1, 2

## CAP NP_3
designator C?
pins: 1, 2

## CAP NP_4
designator C?
pins: 1, 2

## CAP NP_Dup1
designator C?
footprint C0603
pins: 1, 2

## CAP NP_Dup2
designator C?
pins: 1, 2

## CAP NP_Dup3
designator C?
pins: 1, 2

## CAP NP_Dup4
designator C?
pins: 1, 2

## CAP NP_Dup5
designator C?
pins: 1, 2

## CAP_0
designator C?
footprint C0603
pins: 1, 2

## CAP_0.1uF_0603
designator CB?
footprint C0603
pins: 1, 2

## CAP_Dup1
designator C?
pins: 1, 2

## CH7026_0
designator U?
footprint LQFP80
pins: 1 VCOP, 2 VCON, 3 REXT, 4 AVSSP, 5 SSCL, 6 SDDA, 7 RST, 8 DVDD18 (power), 9 DVSS (power), 10 DATA_CLK, 11 DVSS (power), 12 DVDD33 (power), 13 D0, 14 D1, 15 D2, 16 D3, 17 D4, 18 D5, 19 D6, 20 D7, 21 DVDD18 (power), 22 DVSS (power), 23 VSYNC, 24 HSYNC, 25 DE, 26 D8, 27 D9, 28 D10, 29 D11, 30 D12, 31 D13, 32 DVD33 (power), 33 DVSS (power), 34 DVSS (power), 35 DVDD18 (power), 36 D14, 37 D15, 38 D16, 39 D17, 40 D18, 41 D19, 42 D20, 43 D21, 44 D22, 45 D23, 46 SCK/SAUD_CLK, 47 DVDD33 (power), 48 SD0/SAUDO, 49 SD1/SAUD1, 50 DVSS (power), 51 DVDD18 (power), 52 SD2/SAUD2, 53 SD3/SAUD3, 54 VS/SAUD4, 55 MCLK, 56 DSDA, 57 DSCL, 58 INTP/ADDR_SEL, 59 HPD, 60 TEST_EN, 61 DVSS (power), 62 DVSS (power), 63 DVDD18 (power), 64 SPDIF/SAUD5, 65 GPIO, 66 VOREG_C, 67 TXCN, 68 TXCP, 69 AVSS (power), 70 AVSS (power), 71 TX0N, 72 TX0P, 73 VOREG0, 74 VOREG1, 75 TX1N, 76 TX1P, 77 AVSS (power), 78 TX2N, 79 TX2P, 80 VOREG2

## CM3217_0
designator U?
footprint CM3217
pins: 1 GND (power), 2 SDAT (io), 3 SCLK (in), 3 INT, 4 SET, 4 VDD (power)

## CM3217_1
designator U?
footprint CM3217
pins: 1 GND (power), 2 SDAT (io), 3 INT, 4 SET, 5 SCLK (in), 6 VDD (power)

## CMK-CB0077-FV1_6
designator J?
footprint 14-5804-030-000-829
pins: 1 GND_1, 2 RDP0, 3 RDN0, 4 GND_2, 5 RDP2, 6 RDN2, 7 GND_3, 8 RDP3, 9 RDN3, 10 GND_4, 11 MCLK, 12 RESET, 13 XHS, 14 PWDN, 15 FSIN/XVS, 16 VSYNC, 17 AVDD2.8V, 18 AF, 19 GND_5, 20 SIO_C, 21 SIO_D, 22 DVDD, 23 DVDD/GND_6, 24 DOVDD1.8V, 25 GND_7, 26 RDN1, 27 RDP1, 28 GND_8, 29 RCP, 30 RCN, 31 G_31, 32 G_32, 33 G_33, 34 G_34

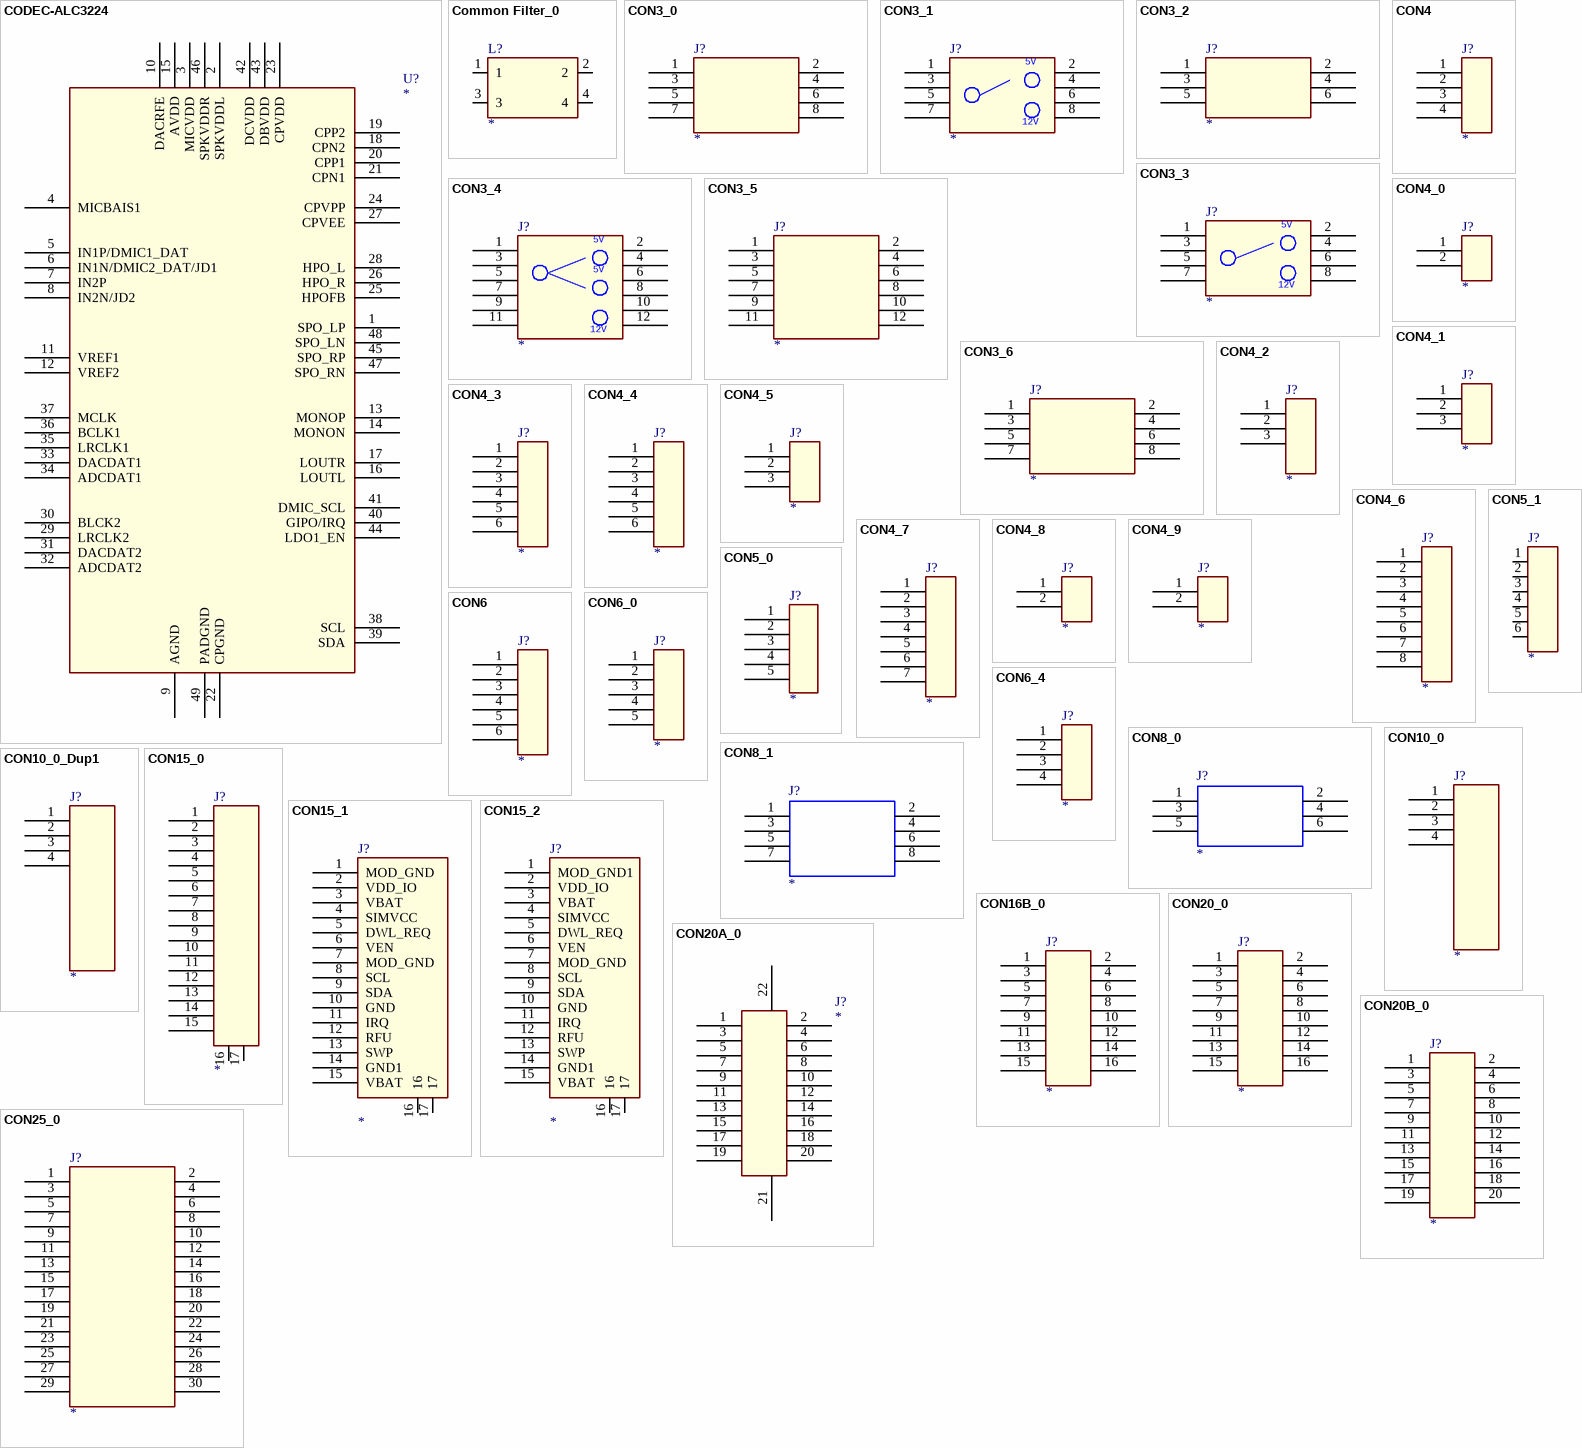
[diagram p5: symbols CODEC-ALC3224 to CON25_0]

## CODEC-ALC3224
designator U?
pins: 1 SPO_LP, 2 SPKVDDL, 3 MICVDD, 4 MICBAIS1, 5 IN1P/DMIC1_DAT, 6 IN1N/DMIC2_DAT/JD1, 7 IN2P, 8 IN2N/JD2, 9 AGND, 10 DACRFE, 11 VREF1, 12 VREF2, 13 MONOP, 14 MONON, 15 AVDD, 16 LOUTL, 17 LOUTR, 18 CPN2, 19 CPP2, 20 CPP1, 21 CPN1, 22 CPGND, 23 CPVDD, 24 CPVPP, 25 HPOFB, 26 HPO_R, 27 CPVEE, 28 HPO_L, 29 LRCLK2, 30 BLCK2, 31 DACDAT2, 32 ADCDAT2, 33 DACDAT1, 34 ADCDAT1, 35 LRCLK1, 36 BCLK1, 37 MCLK, 38 SCL, 39 SDA, 40 GIPO/IRQ, 41 DMIC_SCL, 42 DCVDD, 43 DBVDD, 44 LDO1_EN, 45 SPO_RP, 46 SPKVDDR, 47 SPO_RN, 48 SPO_LN, 49 PADGND

## Common Filter_0
designator L?
pins: 1, 2, 3, 4

## CON3_0
designator J?
pins: 1, 2, 3, 4, 5, 6, 7, 8

## CON3_1
designator J?
pins: 1, 2, 3, 4, 5, 6, 7, 8

## CON3_2
designator J?
pins: 1, 2, 3, 4, 5, 6

## CON3_3
designator J?
pins: 1, 2, 3, 4, 5, 6, 7, 8

## CON3_4
designator J?
pins: 1, 2, 3, 4, 5, 6, 7, 8, 9, 10, 11, 12

## CON3_5
designator J?
pins: 1, 2, 3, 4, 5, 6, 7, 8, 9, 10, 11, 12

## CON3_6
designator J?
pins: 1, 2, 3, 4, 5, 6, 7, 8

## CON4
designator J?
pins: 1, 2, 3, 4

## CON4_0
designator J?
pins: 1, 2

## CON4_1
designator J?
pins: 1, 2, 3

## CON4_2
designator J?
pins: 1, 2, 3

## CON4_3
designator J?
pins: 1, 2, 3, 4, 5 (hiz), 6 (hiz)

## CON4_4
designator J?
pins: 1, 2, 3, 4, 5 (hiz), 6

## CON4_5
designator J?
pins: 1, 2, 3

## CON4_6
designator J?
pins: 1, 2, 3, 4, 5, 6, 7, 8

## CON4_7
designator J?
pins: 1, 2, 3, 4, 5, 6, 7

## CON4_8
designator J?
pins: 1, 2

## CON4_9
designator J?
pins: 1, 2

## CON5_0
designator J?
pins: 1, 2, 3, 4, 5

## CON5_1
designator J?
pins: 1, 2, 3, 4, 5, 6

## CON6
designator J?
pins: 1, 2, 3, 4, 5, 6

## CON6_0
designator J?
pins: 1, 2, 3, 4, 5

## CON6_4
designator J?
pins: 1, 2, 3, 4

## CON8_0
designator J?
pins: 1, 2, 3, 4, 5, 6

## CON8_1
designator J?
pins: 1, 2, 3, 4, 5, 6, 7, 8

## CON10_0
designator J?
pins: 1, 2, 3, 4

## CON10_0_Dup1
designator J?
pins: 1, 2, 3, 4

## CON15_0
designator J?
pins: 1, 2, 3, 4, 5, 6, 7, 8, 9, 10, 11, 12, 13, 14, 15, 16, 17

## CON15_1
designator J?
pins: 1 MOD_GND, 2 VDD_IO, 3 VBAT, 4 SIMVCC, 5 DWL_REQ, 6 VEN, 7 MOD_GND, 8 SCL, 9 SDA, 10 GND, 11 IRQ, 12 RFU, 13 SWP, 14 GND1, 15 VBAT, 16, 17

## CON15_2
designator J?
pins: 1 MOD_GND1, 2 VDD_IO, 3 VBAT (power), 4 SIMVCC, 5 DWL_REQ, 6 VEN, 7 MOD_GND, 8 SCL, 9 SDA, 10 GND, 11 IRQ, 12 RFU, 13 SWP, 14 GND1, 15 VBAT (power), 16, 17

## CON16B_0
designator J?
pins: 1, 2, 3, 4, 5, 6, 7, 8, 9, 10, 11, 12, 13, 14, 15, 16

## CON20_0
designator J?
pins: 1, 2, 3, 4, 5, 6, 7, 8, 9, 10, 11, 12, 13, 14, 15, 16

## CON20A_0
designator J?
pins: 1, 2, 3, 4, 5, 6, 7, 8, 9, 10, 11, 12, 13, 14, 15, 16, 17, 18, 19, 20, 21, 22

## CON20B_0
designator J?
pins: 1, 2, 3, 4, 5, 6, 7, 8, 9, 10, 11, 12, 13, 14, 15, 16, 17, 18, 19, 20

## CON25_0
designator J?
pins: 1, 2, 3, 4, 5, 6, 7, 8, 9, 10, 11, 12, 13, 14, 15, 16, 17, 18, 19, 20, 21, 22, 23, 24, 25, 26, 27, 28, 29, 30

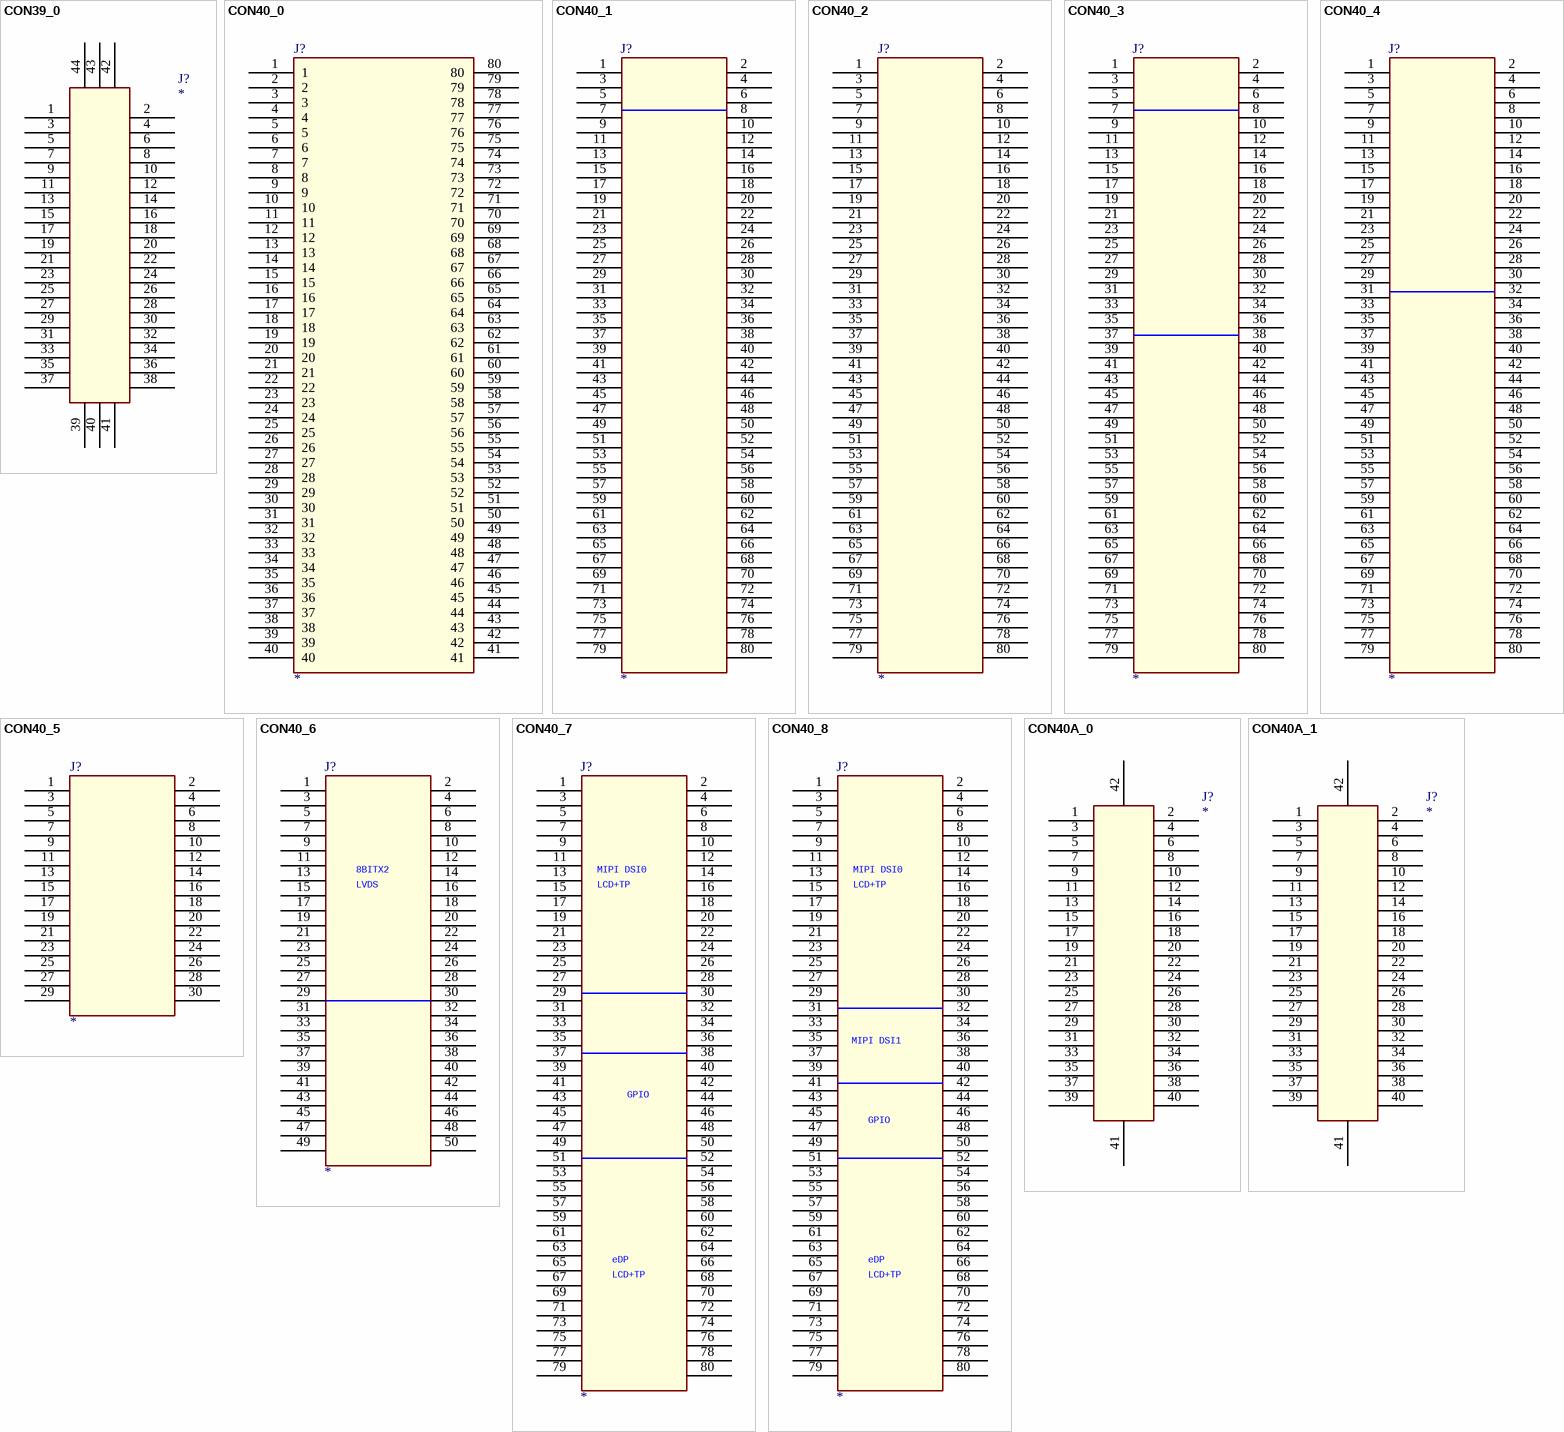
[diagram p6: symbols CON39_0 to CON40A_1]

## CON39_0
designator J?
pins: 1, 2, 3, 4, 5, 6, 7, 8, 9, 10, 11, 12, 13, 14, 15, 16, 17, 18, 19, 20, 21, 22, 23, 24, 25, 26, 27, 28, 29, 30, 31, 32, 33, 34, 35, 36, 37, 38, 39, 40, 41, 42, 43, 44

## CON40_0
designator J?
pins: 1, 2, 3, 4, 5, 6, 7, 8, 9, 10, 11, 12, 13, 14, 15, 16, 17, 18, 19, 20, 21, 22, 23, 24, 25, 26, 27, 28, 29, 30, 31, 32, 33, 34, 35, 36, 37, 38, 39, 40, 41, 42, 43, 44, 45, 46, 47, 48, 49, 50, 51, 52, 53, 54, 55, 56, 57, 58, 59, 60, 61, 62, 63, 64, 65, 66, 67, 68, 69, 70, 71, 72, 73, 74, 75, 76, 77, 78, 79, 80

## CON40_1
designator J?
pins: 1, 2, 3, 4, 5, 6, 7, 8, 9, 10, 11, 12, 13, 14, 15, 16, 17, 18, 19, 20, 21, 22, 23, 24, 25, 26, 27, 28, 29, 30, 31, 32, 33, 34, 35, 36, 37, 38, 39, 40, 41, 42, 43, 44, 45, 46, 47, 48, 49, 50, 51, 52, 53, 54, 55, 56, 57, 58, 59, 60, 61, 62, 63, 64, 65, 66, 67, 68, 69, 70, 71, 72, 73, 74, 75, 76, 77, 78, 79, 80

## CON40_2
designator J?
pins: 1, 2, 3, 4, 5, 6, 7, 8, 9, 10, 11, 12, 13, 14, 15, 16, 17, 18, 19, 20, 21, 22, 23, 24, 25, 26, 27, 28, 29, 30, 31, 32, 33, 34, 35, 36, 37, 38, 39, 40, 41, 42, 43, 44, 45, 46, 47, 48, 49, 50, 51, 52, 53, 54, 55, 56, 57, 58, 59, 60, 61, 62, 63, 64, 65, 66, 67, 68, 69, 70, 71, 72, 73, 74, 75, 76, 77, 78, 79, 80

## CON40_3
designator J?
pins: 1, 2, 3, 4, 5, 6, 7, 8, 9, 10, 11, 12, 13, 14, 15, 16, 17, 18, 19, 20, 21, 22, 23, 24, 25, 26, 27, 28, 29, 30, 31, 32, 33, 34, 35, 36, 37, 38, 39, 40, 41, 42, 43, 44, 45, 46, 47, 48, 49, 50, 51, 52, 53, 54, 55, 56, 57, 58, 59, 60, 61, 62, 63, 64, 65, 66, 67, 68, 69, 70, 71, 72, 73, 74, 75, 76, 77, 78, 79, 80

## CON40_4
designator J?
pins: 1, 2, 3, 4, 5, 6, 7, 8, 9, 10, 11, 12, 13, 14, 15, 16, 17, 18, 19, 20, 21, 22, 23, 24, 25, 26, 27, 28, 29, 30, 31, 32, 33, 34, 35, 36, 37, 38, 39, 40, 41, 42, 43, 44, 45, 46, 47, 48, 49, 50, 51, 52, 53, 54, 55, 56, 57, 58, 59, 60, 61, 62, 63, 64, 65, 66, 67, 68, 69, 70, 71, 72, 73, 74, 75, 76, 77, 78, 79, 80

## CON40_5
designator J?
pins: 1, 2, 3, 4, 5, 6, 7, 8, 9, 10, 11, 12, 13, 14, 15, 16, 17, 18, 19, 20, 21, 22, 23, 24, 25, 26, 27, 28, 29, 30

## CON40_6
designator J?
pins: 1, 2, 3, 4, 5, 6, 7, 8, 9, 10, 11, 12, 13, 14, 15, 16, 17, 18, 19, 20, 21, 22, 23, 24, 25, 26, 27, 28, 29, 30, 31, 32, 33, 34, 35, 36, 37, 38, 39, 40, 41, 42, 43, 44, 45, 46, 47, 48, 49, 50

## CON40_7
designator J?
pins: 1, 2, 3, 4, 5, 6, 7, 8, 9, 10, 11, 12, 13, 14, 15, 16, 17, 18, 19, 20, 21, 22, 23, 24, 25, 26, 27, 28, 29, 30, 31, 32, 33, 34, 35, 36, 37, 38, 39, 40, 41, 42, 43, 44, 45, 46, 47, 48, 49, 50, 51, 52, 53, 54, 55, 56, 57, 58, 59, 60, 61, 62, 63, 64, 65, 66, 67, 68, 69, 70, 71, 72, 73, 74, 75, 76, 77, 78, 79, 80

## CON40_8
designator J?
pins: 1, 2, 3, 4, 5, 6, 7, 8, 9, 10, 11, 12, 13, 14, 15, 16, 17, 18, 19, 20, 21, 22, 23, 24, 25, 26, 27, 28, 29, 30, 31, 32, 33, 34, 35, 36, 37, 38, 39, 40, 41, 42, 43, 44, 45, 46, 47, 48, 49, 50, 51, 52, 53, 54, 55, 56, 57, 58, 59, 60, 61, 62, 63, 64, 65, 66, 67, 68, 69, 70, 71, 72, 73, 74, 75, 76, 77, 78, 79, 80

## CON40A_0
designator J?
pins: 1, 2, 3, 4, 5, 6, 7, 8, 9, 10, 11, 12, 13, 14, 15, 16, 17, 18, 19, 20, 21, 22, 23, 24, 25, 26, 27, 28, 29, 30, 31, 32, 33, 34, 35, 36, 37, 38, 39, 40, 41, 42

## CON40A_1
designator J?
pins: 1, 2, 3, 4, 5, 6, 7, 8, 9, 10, 11, 12, 13, 14, 15, 16, 17, 18, 19, 20, 21, 22, 23, 24, 25, 26, 27, 28, 29, 30, 31, 32, 33, 34, 35, 36, 37, 38, 39, 40, 41, 42

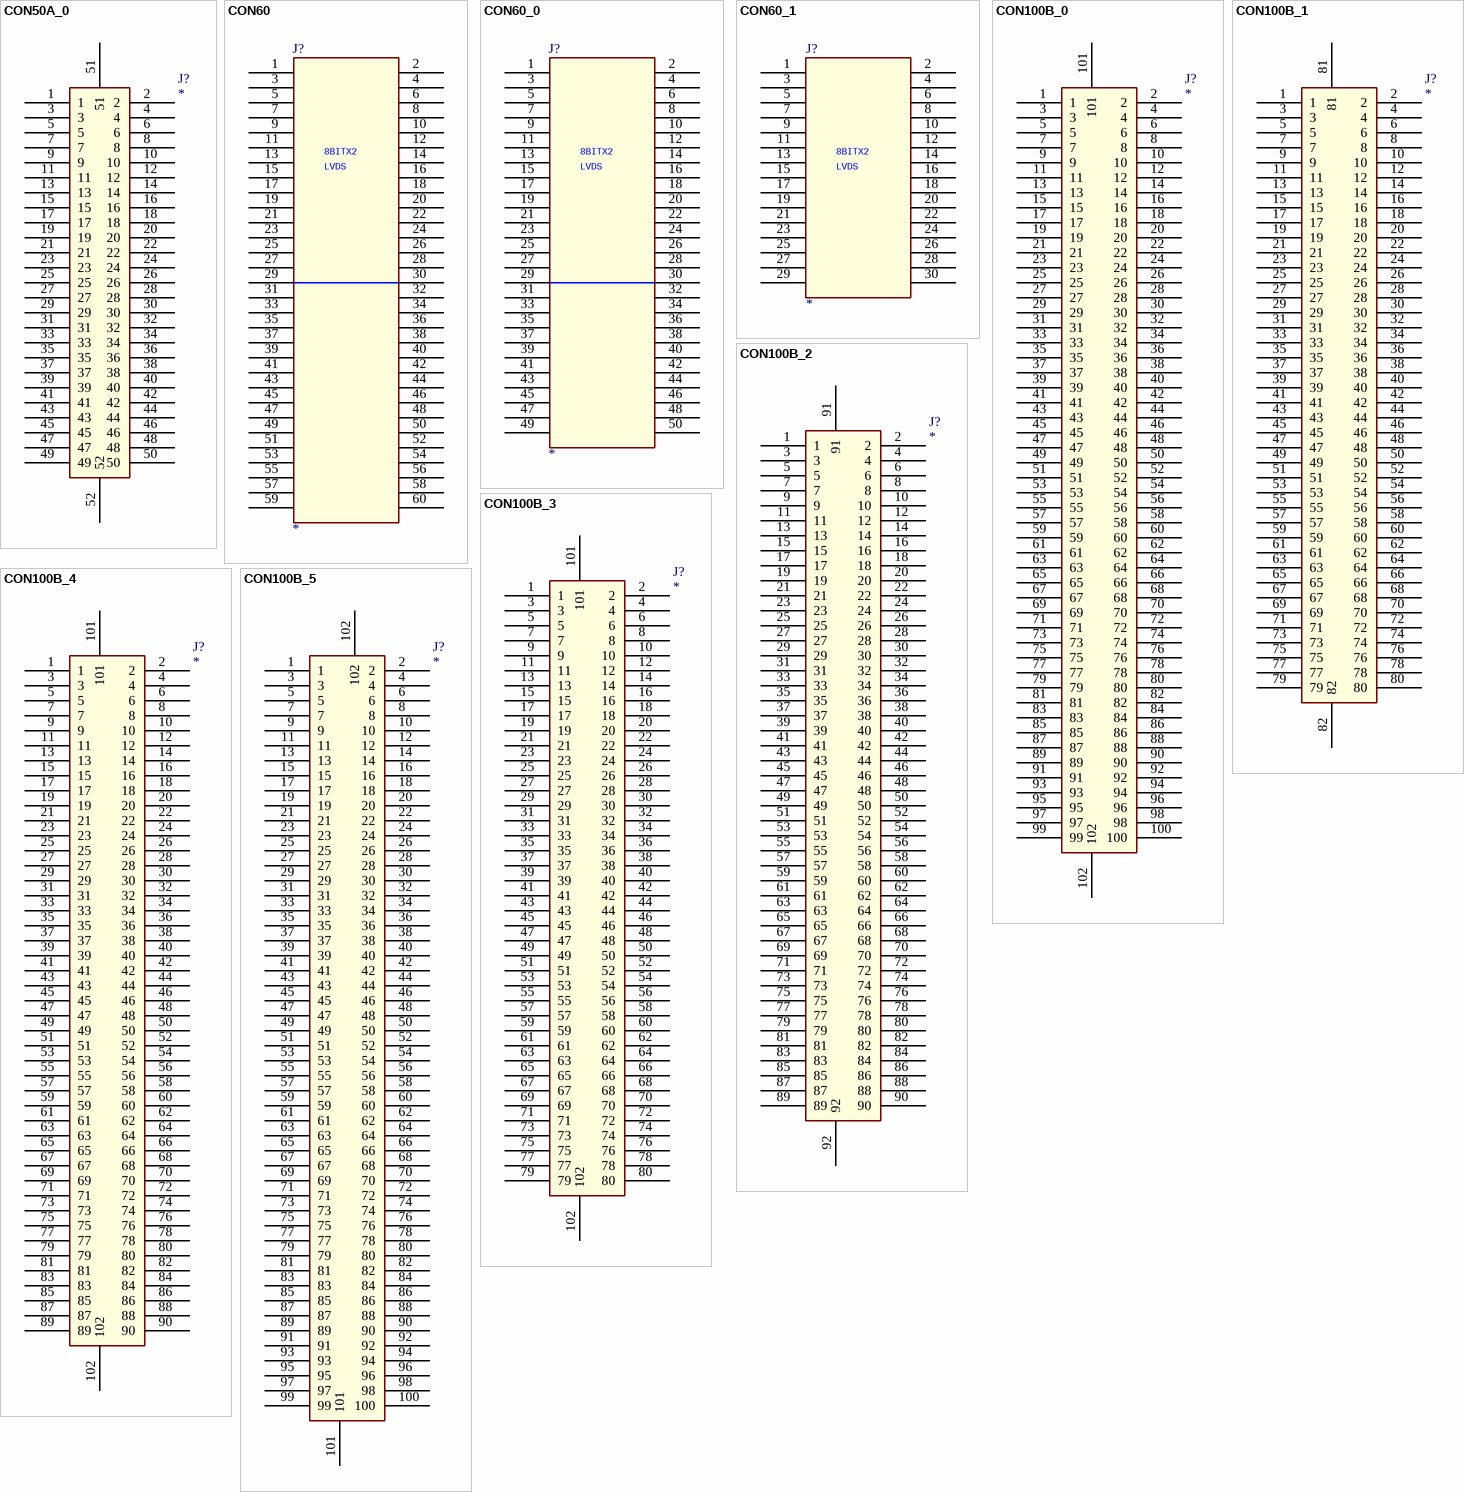
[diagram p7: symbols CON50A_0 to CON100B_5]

## CON50A_0
designator J?
footprint 25PIN-S2.54
pins: 1, 2, 3, 4, 5, 6, 7, 8, 9, 10, 11, 12, 13, 14, 15, 16, 17, 18, 19, 20, 21, 22, 23, 24, 25, 26, 27, 28, 29, 30, 31, 32, 33, 34, 35, 36, 37, 38, 39, 40, 41, 42, 43, 44, 45, 46, 47, 48, 49, 50, 51, 52

## CON60
designator J?
pins: 1, 2, 3, 4, 5, 6, 7, 8, 9, 10, 11, 12, 13, 14, 15, 16, 17, 18, 19, 20, 21, 22, 23, 24, 25, 26, 27, 28, 29, 30, 31, 32, 33, 34, 35, 36, 37, 38, 39, 40, 41, 42, 43, 44, 45, 46, 47, 48, 49, 50, 51, 52, 53, 54, 55, 56, 57, 58, 59, 60

## CON60_0
designator J?
pins: 1, 2, 3, 4, 5, 6, 7, 8, 9, 10, 11, 12, 13, 14, 15, 16, 17, 18, 19, 20, 21, 22, 23, 24, 25, 26, 27, 28, 29, 30, 31, 32, 33, 34, 35, 36, 37, 38, 39, 40, 41, 42, 43, 44, 45, 46, 47, 48, 49, 50

## CON60_1
designator J?
pins: 1, 2, 3, 4, 5, 6, 7, 8, 9, 10, 11, 12, 13, 14, 15, 16, 17, 18, 19, 20, 21, 22, 23, 24, 25, 26, 27, 28, 29, 30

## CON100B_0
designator J?
footprint 50PIN-S1.27
pins: 1, 2, 3, 4, 5, 6, 7, 8, 9, 10, 11, 12, 13, 14, 15, 16, 17, 18, 19, 20, 21, 22, 23, 24, 25, 26, 27, 28, 29, 30, 31, 32, 33, 34, 35, 36, 37, 38, 39, 40, 41, 42, 43, 44, 45, 46, 47, 48, 49, 50, 51, 52, 53, 54, 55, 56, 57, 58, 59, 60, 61, 62, 63, 64, 65, 66, 67, 68, 69, 70, 71, 72, 73, 74, 75, 76, 77, 78, 79, 80, 81, 82, 83, 84, 85, 86, 87, 88, 89, 90, 91, 92, 93, 94, 95, 96, 97, 98, 99, 100, 101, 102

## CON100B_1
designator J?
footprint 50PIN-S1.27
pins: 1, 2, 3, 4, 5, 6, 7, 8, 9, 10, 11, 12, 13, 14, 15, 16, 17, 18, 19, 20, 21, 22, 23, 24, 25, 26, 27, 28, 29, 30, 31, 32, 33, 34, 35, 36, 37, 38, 39, 40, 41, 42, 43, 44, 45, 46, 47, 48, 49, 50, 51, 52, 53, 54, 55, 56, 57, 58, 59, 60, 61, 62, 63, 64, 65, 66, 67, 68, 69, 70, 71, 72, 73, 74, 75, 76, 77, 78, 79, 80, 81, 82

## CON100B_2
designator J?
footprint 50PIN-S1.27
pins: 1, 2, 3, 4, 5, 6, 7, 8, 9, 10, 11, 12, 13, 14, 15, 16, 17, 18, 19, 20, 21, 22, 23, 24, 25, 26, 27, 28, 29, 30, 31, 32, 33, 34, 35, 36, 37, 38, 39, 40, 41, 42, 43, 44, 45, 46, 47, 48, 49, 50, 51, 52, 53, 54, 55, 56, 57, 58, 59, 60, 61, 62, 63, 64, 65, 66, 67, 68, 69, 70, 71, 72, 73, 74, 75, 76, 77, 78, 79, 80, 81, 82, 83, 84, 85, 86, 87, 88, 89, 90, 91, 92

## CON100B_3
designator J?
footprint 50PIN-S1.27
pins: 1, 2, 3, 4, 5, 6, 7, 8, 9, 10, 11, 12, 13, 14, 15, 16, 17, 18, 19, 20, 21, 22, 23, 24, 25, 26, 27, 28, 29, 30, 31, 32, 33, 34, 35, 36, 37, 38, 39, 40, 41, 42, 43, 44, 45, 46, 47, 48, 49, 50, 51, 52, 53, 54, 55, 56, 57, 58, 59, 60, 61, 62, 63, 64, 65, 66, 67, 68, 69, 70, 71, 72, 73, 74, 75, 76, 77, 78, 79, 80, 101, 102

## CON100B_4
designator J?
footprint 50PIN-S1.27
pins: 1, 2, 3, 4, 5, 6, 7, 8, 9, 10, 11, 12, 13, 14, 15, 16, 17, 18, 19, 20, 21, 22, 23, 24, 25, 26, 27, 28, 29, 30, 31, 32, 33, 34, 35, 36, 37, 38, 39, 40, 41, 42, 43, 44, 45, 46, 47, 48, 49, 50, 51, 52, 53, 54, 55, 56, 57, 58, 59, 60, 61, 62, 63, 64, 65, 66, 67, 68, 69, 70, 71, 72, 73, 74, 75, 76, 77, 78, 79, 80, 81, 82, 83, 84, 85, 86, 87, 88, 89, 90, 101, 102

## CON100B_5
designator J?
footprint 50PIN-S1.27
pins: 1, 2, 3, 4, 5, 6, 7, 8, 9, 10, 11, 12, 13, 14, 15, 16, 17, 18, 19, 20, 21, 22, 23, 24, 25, 26, 27, 28, 29, 30, 31, 32, 33, 34, 35, 36, 37, 38, 39, 40, 41, 42, 43, 44, 45, 46, 47, 48, 49, 50, 51, 52, 53, 54, 55, 56, 57, 58, 59, 60, 61, 62, 63, 64, 65, 66, 67, 68, 69, 70, 71, 72, 73, 74, 75, 76, 77, 78, 79, 80, 81, 82, 83, 84, 85, 86, 87, 88, 89, 90, 91, 92, 93, 94, 95, 96, 97, 98, 99, 100, 101, 102

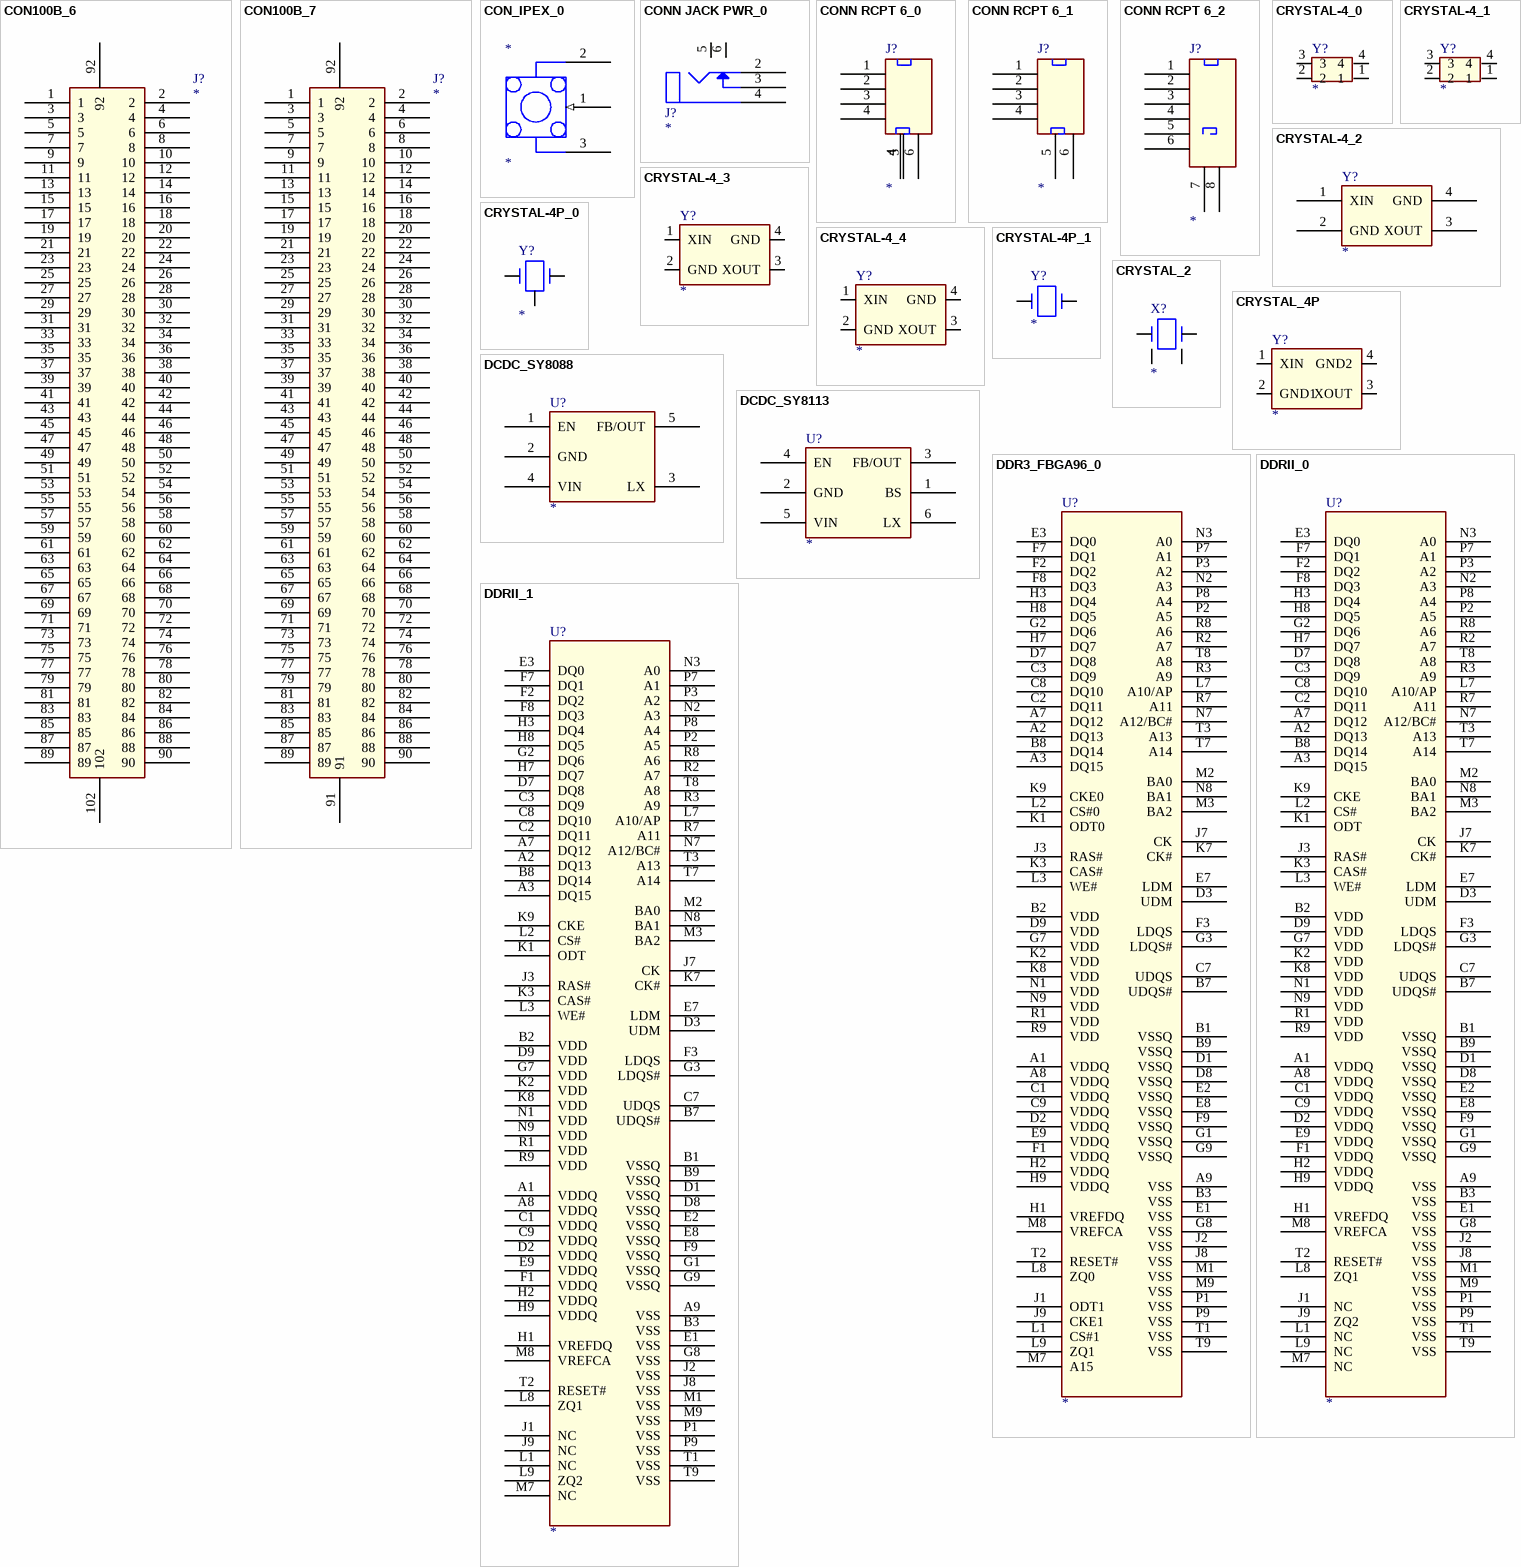
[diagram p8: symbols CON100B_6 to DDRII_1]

## CON100B_6
designator J?
footprint 50PIN-S1.27
pins: 1, 2, 3, 4, 5, 6, 7, 8, 9, 10, 11, 12, 13, 14, 15, 16, 17, 18, 19, 20, 21, 22, 23, 24, 25, 26, 27, 28, 29, 30, 31, 32, 33, 34, 35, 36, 37, 38, 39, 40, 41, 42, 43, 44, 45, 46, 47, 48, 49, 50, 51, 52, 53, 54, 55, 56, 57, 58, 59, 60, 61, 62, 63, 64, 65, 66, 67, 68, 69, 70, 71, 72, 73, 74, 75, 76, 77, 78, 79, 80, 81, 82, 83, 84, 85, 86, 87, 88, 89, 90, 92, 102

## CON100B_7
designator J?
footprint 50PIN-S1.27
pins: 1, 2, 3, 4, 5, 6, 7, 8, 9, 10, 11, 12, 13, 14, 15, 16, 17, 18, 19, 20, 21, 22, 23, 24, 25, 26, 27, 28, 29, 30, 31, 32, 33, 34, 35, 36, 37, 38, 39, 40, 41, 42, 43, 44, 45, 46, 47, 48, 49, 50, 51, 52, 53, 54, 55, 56, 57, 58, 59, 60, 61, 62, 63, 64, 65, 66, 67, 68, 69, 70, 71, 72, 73, 74, 75, 76, 77, 78, 79, 80, 81, 82, 83, 84, 85, 86, 87, 88, 89, 90, 91, 92

## CON_IPEX_0
designator *
?; OriginalSymbolOrigin: (-100,200)
pins: 1 IN (in), 2 GND1 (power), 3 GND2 (power)

## CONN JACK PWR_0
designator J?
pins: 2, 3, 4, 5, 6

## CONN RCPT 6_0
designator J?
pins: 1, 2, 3, 4, 4, 4, 4, 5, 6

## CONN RCPT 6_1
designator J?
pins: 1, 2, 3, 4, 5, 6

## CONN RCPT 6_2
designator J?
pins: 1, 2, 3, 4, 5, 6, 7, 8

## CRYSTAL-4_0
designator Y?
footprint CRY-3225
pins: 1, 2, 3, 4 (power)

## CRYSTAL-4_1
designator Y?
footprint CRY-3225
pins: 1, 2, 3, 4

## CRYSTAL-4_2
designator Y?
footprint CRY-3225
pins: 1 XIN, 2 GND (power), 3 XOUT, 4 GND (power)

## CRYSTAL-4_3
designator Y?
footprint CRY-3225
pins: 1 XIN, 2 GND (power), 3 XOUT, 4 GND (power)

## CRYSTAL-4_4
designator Y?
footprint CRY-3225
pins: 1 XIN, 2 GND (power), 3 XOUT, 4 GND (power)

## CRYSTAL-4P_0
designator Y?
pins: 1, 2, 3

## CRYSTAL-4P_1
designator Y?
pins: 1, 2

## CRYSTAL_2
designator X?
pins: 1, 2, 3, 4

## CRYSTAL_4P
designator Y?
footprint CRY-3225
pins: 1 XIN, 2 GND1, 3 XOUT, 4 GND2

## DCDC_SY8088
designator U?
pins: 1 EN, 2 GND, 3 LX, 4 VIN, 5 FB/OUT

## DCDC_SY8113
designator U?
pins: 1 BS, 2 GND, 3 FB/OUT, 4 EN, 5 VIN, 6 LX

## DDR3_FBGA96_0
designator U?
footprint DDRII_X16
pins: A1 VDDQ (power), A2 DQ13, A3 DQ15, A7 DQ12, A8 VDDQ (power), A9 VSS (power), B1 VSSQ (power), B2 VDD (power), B3 VSS (power), B7 UDQS#, B8 DQ14, B9 VSSQ (power), C1 VDDQ (power), C2 DQ11, C3 DQ9, C7 UDQS, C8 DQ10, C9 VDDQ (power), D1 VSSQ (power), D2 VDDQ (power), D3 UDM, D7 DQ8, D8 VSSQ (power), D9 VDD (power), E1 VSS (power), E2 VSSQ (power), E3 DQ0, E7 LDM, E8 VSSQ (power), E9 VDDQ (power), F1 VDDQ (power), F2 DQ2, F3 LDQS, F7 DQ1, F8 DQ3, F9 VSSQ (power), G1 VSSQ (power), G2 DQ6, G3 LDQS#, G7 VDD (power), G8 VSS (power), G9 VSSQ (power), H1 VREFDQ, H2 VDDQ (power), H3 DQ4, H7 DQ7, H8 DQ5, H9 VDDQ (power), J1 ODT1, J2 VSS (power), J3 RAS#, J7 CK, J8 VSS (power), J9 CKE1, K1 ODT0, K2 VDD (power), K3 CAS#, K7 CK#, K8 VDD (power), K9 CKE0, L1 CS#1, L2 CS#0, L3 WE#, L7 A10/AP, L8 ZQ0, L9 ZQ1, M1 VSS (power), M2 BA0, M3 BA2, M7 A15, M8 VREFCA, M9 VSS (power), N1 VDD (power), N2 A3, N3 A0, N7 A12/BC#, N8 BA1, N9 VDD (power), P1 VSS (power), P2 A5, P3 A2, P7 A1, P8 A4, P9 VSS (power), R1 VDD (power), R2 A7, R3 A9, R7 A11, R8 A6, R9 VDD (power), T1 VSS (power), T2 RESET#, T3 A13, T7 A14, T8 A8, T9 VSS (power)

## DDRII_0
designator U?
footprint DDRII_X16
pins: A1 VDDQ, A2 DQ13, A3 DQ15, A7 DQ12, A8 VDDQ, A9 VSS, B1 VSSQ, B2 VDD, B3 VSS, B7 UDQS#, B8 DQ14, B9 VSSQ, C1 VDDQ, C2 DQ11, C3 DQ9, C7 UDQS, C8 DQ10, C9 VDDQ, D1 VSSQ, D2 VDDQ, D3 UDM, D7 DQ8, D8 VSSQ, D9 VDD, E1 VSS, E2 VSSQ, E3 DQ0, E7 LDM, E8 VSSQ, E9 VDDQ, F1 VDDQ, F2 DQ2, F3 LDQS, F7 DQ1, F8 DQ3, F9 VSSQ, G1 VSSQ, G2 DQ6, G3 LDQS#, G7 VDD, G8 VSS, G9 VSSQ, H1 VREFDQ, H2 VDDQ, H3 DQ4, H7 DQ7, H8 DQ5, H9 VDDQ, J1 NC, J2 VSS, J3 RAS#, J7 CK, J8 VSS, J9 ZQ2, K1 ODT, K2 VDD, K3 CAS#, K7 CK#, K8 VDD, K9 CKE, L1 NC, L2 CS#, L3 WE#, L7 A10/AP, L8 ZQ1, L9 NC, M1 VSS, M2 BA0, M3 BA2, M7 NC, M8 VREFCA, M9 VSS, N1 VDD, N2 A3, N3 A0, N7 A12/BC#, N8 BA1, N9 VDD, P1 VSS, P2 A5, P3 A2, P7 A1, P8 A4, P9 VSS, R1 VDD, R2 A7, R3 A9, R7 A11, R8 A6, R9 VDD, T1 VSS, T2 RESET#, T3 A13, T7 A14, T8 A8, T9 VSS

## DDRII_1
designator U?
footprint DDRII_X16
pins: A1 VDDQ, A2 DQ13, A3 DQ15, A7 DQ12, A8 VDDQ, A9 VSS, B1 VSSQ, B2 VDD, B3 VSS, B7 UDQS#, B8 DQ14, B9 VSSQ, C1 VDDQ, C2 DQ11, C3 DQ9, C7 UDQS, C8 DQ10, C9 VDDQ, D1 VSSQ, D2 VDDQ, D3 UDM, D7 DQ8, D8 VSSQ, D9 VDD, E1 VSS, E2 VSSQ, E3 DQ0, E7 LDM, E8 VSSQ, E9 VDDQ, F1 VDDQ, F2 DQ2, F3 LDQS, F7 DQ1, F8 DQ3, F9 VSSQ, G1 VSSQ, G2 DQ6, G3 LDQS#, G7 VDD, G8 VSS, G9 VSSQ, H1 VREFDQ, H2 VDDQ, H3 DQ4, H7 DQ7, H8 DQ5, H9 VDDQ, J1 NC, J2 VSS, J3 RAS#, J7 CK, J8 VSS, J9 NC, K1 ODT, K2 VDD, K3 CAS#, K7 CK#, K8 VDD, K9 CKE, L1 NC, L2 CS#, L3 WE#, L7 A10/AP, L8 ZQ1, L9 ZQ2, M1 VSS, M2 BA0, M3 BA2, M7 NC, M8 VREFCA, M9 VSS, N1 VDD, N2 A3, N3 A0, N7 A12/BC#, N8 BA1, N9 VDD, P1 VSS, P2 A5, P3 A2, P7 A1, P8 A4, P9 VSS, R1 VDD, R2 A7, R3 A9, R7 A11, R8 A6, R9 VDD, T1 VSS, T2 RESET#, T3 A13, T7 A14, T8 A8, T9 VSS

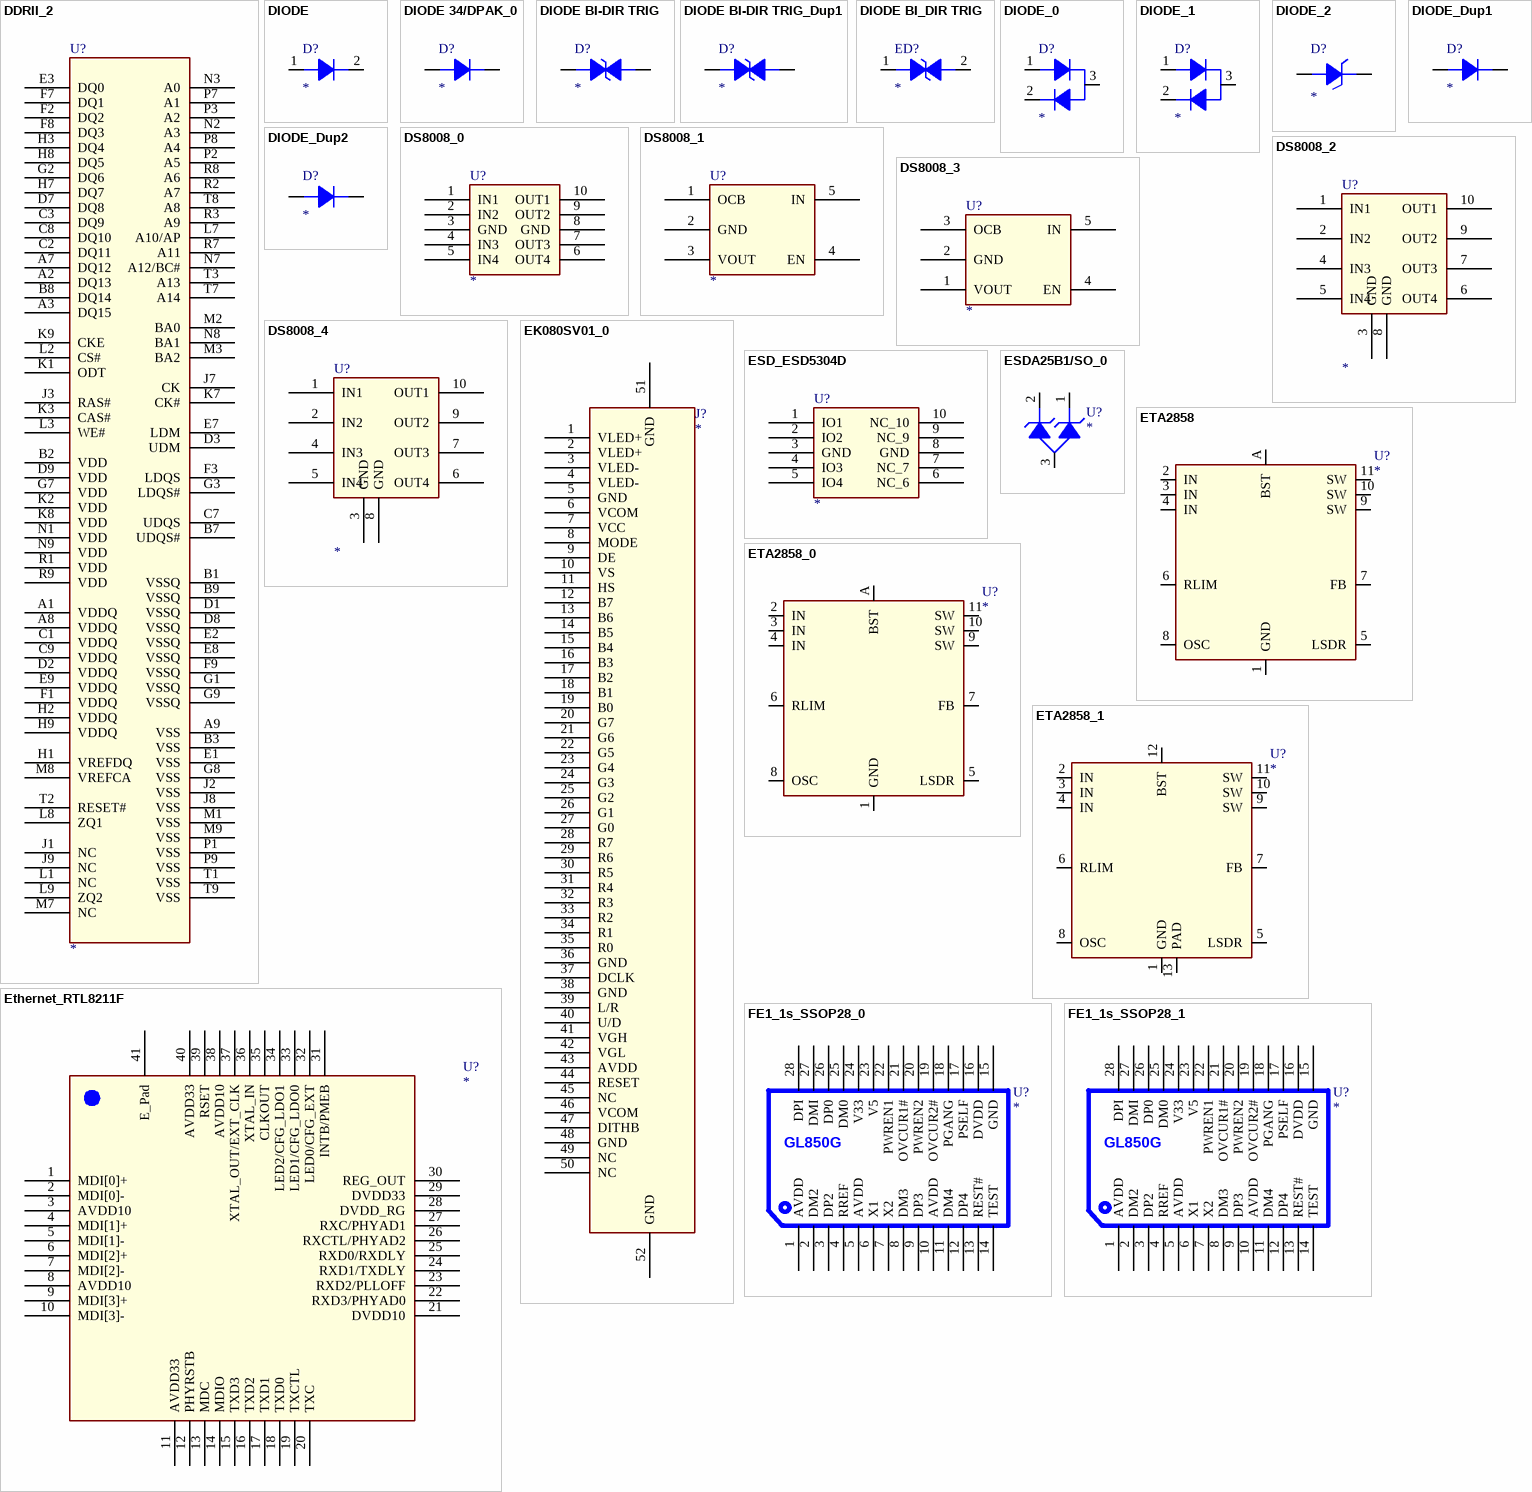
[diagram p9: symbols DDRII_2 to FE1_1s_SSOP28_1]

## DDRII_2
designator U?
footprint DDRII_X16
pins: A1 VDDQ, A2 DQ13, A3 DQ15, A7 DQ12, A8 VDDQ, A9 VSS, B1 VSSQ, B2 VDD, B3 VSS, B7 UDQS#, B8 DQ14, B9 VSSQ, C1 VDDQ, C2 DQ11, C3 DQ9, C7 UDQS, C8 DQ10, C9 VDDQ, D1 VSSQ, D2 VDDQ, D3 UDM, D7 DQ8, D8 VSSQ, D9 VDD, E1 VSS, E2 VSSQ, E3 DQ0, E7 LDM, E8 VSSQ, E9 VDDQ, F1 VDDQ, F2 DQ2, F3 LDQS, F7 DQ1, F8 DQ3, F9 VSSQ, G1 VSSQ, G2 DQ6, G3 LDQS#, G7 VDD, G8 VSS, G9 VSSQ, H1 VREFDQ, H2 VDDQ, H3 DQ4, H7 DQ7, H8 DQ5, H9 VDDQ, J1 NC, J2 VSS, J3 RAS#, J7 CK, J8 VSS, J9 NC, K1 ODT, K2 VDD, K3 CAS#, K7 CK#, K8 VDD, K9 CKE, L1 NC, L2 CS#, L3 WE#, L7 A10/AP, L8 ZQ1, L9 ZQ2, M1 VSS, M2 BA0, M3 BA2, M7 NC, M8 VREFCA, M9 VSS, N1 VDD, N2 A3, N3 A0, N7 A12/BC#, N8 BA1, N9 VDD, P1 VSS, P2 A5, P3 A2, P7 A1, P8 A4, P9 VSS, R1 VDD, R2 A7, R3 A9, R7 A11, R8 A6, R9 VDD, T1 VSS, T2 RESET#, T3 A13, T7 A14, T8 A8, T9 VSS

## DIODE
designator D?
pins: 1 A, 2 K

## DIODE 34/DPAK_0
designator D?
pins: 1 ANODE, 2 CATHODE

## DIODE BI-DIR TRIG
designator D?
pins: 1, 2

## DIODE BI-DIR TRIG_Dup1
designator D?
pins: 1, 2

## DIODE BI_DIR TRIG
designator ED?
pins: 1, 2

## DIODE_0
designator D?
pins: 1 ANODE, 2 CATHODE, 3 COMMON

## DIODE_1
designator D?
pins: 1 ANODE, 2 CATHODE, 3 COMMON

## DIODE_2
designator D?
pins: 1 A, 2 K

## DIODE_Dup1
designator D?
pins: 1 A, 2 K

## DIODE_Dup2
designator D?
pins: 1 A, 2 K

## DS8008_0
designator U?
pins: 1 IN1, 2 IN2, 3 GND (power), 4 IN3, 5 IN4, 6 OUT4, 7 OUT3, 8 GND (power), 9 OUT2, 10 OUT1

## DS8008_1
designator U?
pins: 1 OCB, 2 GND, 3 VOUT, 4 EN, 5 IN

## DS8008_2
designator U?
pins: 1 IN1, 2 IN2, 3 GND (power), 4 IN3, 5 IN4, 6 OUT4, 7 OUT3, 8 GND, 9 OUT2, 10 OUT1

## DS8008_3
designator U?
pins: 1 VOUT, 2 GND, 3 OCB, 4 EN, 5 IN

## DS8008_4
designator U?
pins: 1 IN1, 2 IN2, 3 GND (power), 4 IN3, 5 IN4, 6 OUT4, 7 OUT3, 8 GND (power), 9 OUT2, 10 OUT1

## EK080SV01_0
designator J?
pins: 1 VLED+, 2 VLED+, 3 VLED-, 4 VLED-, 5 GND, 6 VCOM, 7 VCC, 8 MODE, 9 DE, 10 VS, 11 HS, 12 B7, 13 B6, 14 B5, 15 B4, 16 B3, 17 B2, 18 B1, 19 B0, 20 G7, 21 G6, 22 G5, 23 G4, 24 G3, 25 G2, 26 G1, 27 G0, 28 R7, 29 R6, 30 R5, 31 R4, 32 R3, 33 R2, 34 R1, 35 R0, 36 GND, 37 DCLK, 38 GND, 39 L/R, 40 U/D, 41 VGH, 42 VGL, 43 AVDD, 44 RESET, 45 NC, 46 VCOM, 47 DITHB, 48 GND, 49 NC, 50 NC, 51 GND, 52 GND

## ESD_ESD5304D
designator U?
pins: 1 IO1, 2 IO2, 3 GND (power), 4 IO3, 5 IO4, 6 NC_6, 7 NC_7, 8 GND (power), 9 NC_9, 10 NC_10

## ESDA25B1/SO_0
designator U?
pins: 1, 2, 3

## ETA2858
designator U?
pins: 1 GND, 2 IN (power), 3 IN (power), 4 IN (power), 5 LSDR, 6 RLIM, 7 FB, 8 OSC, 9 SW (power), 10 SW (power), 11 SW (power), A BST

## ETA2858_0
designator U?
pins: 1 GND, 2 IN (power), 3 IN (power), 4 IN (power), 5 LSDR, 6 RLIM, 7 FB, 8 OSC, 9 SW (power), 10 SW (power), 11 SW (power), A BST

## ETA2858_1
designator U?
pins: 1 GND, 2 IN (power), 3 IN (power), 4 IN (power), 5 LSDR, 6 RLIM, 7 FB, 8 OSC, 9 SW (power), 10 SW (power), 11 SW (power), 12 BST, 13 PAD

## Ethernet_RTL8211F
designator U?
footprint QFN40_5R00X5R00X0R80_T
pins: 1 MDI[0]+, 2 MDI[0]-, 3 AVDD10 (power), 4 MDI[1]+, 5 MDI[1]-, 6 MDI[2]+, 7 MDI[2]-, 8 AVDD10 (power), 9 MDI[3]+, 10 MDI[3]-, 11 AVDD33 (power), 12 PHYRSTB, 13 MDC, 14 MDIO, 15 TXD3, 16 TXD2, 17 TXD1, 18 TXD0, 19 TXCTL, 20 TXC, 21 DVDD10 (power), 22 RXD3/PHYAD0, 23 RXD2/PLLOFF, 24 RXD1/TXDLY, 25 RXD0/RXDLY, 26 RXCTL/PHYAD2, 27 RXC/PHYAD1, 28 DVDD_RG, 29 DVDD33 (power), 30 REG_OUT, 31 INTB/PMEB, 32 LED0/CFG_EXT, 33 LED1/CFG_LDO0, 34 LED2/CFG_LDO1, 35 CLKOUT, 36 XTAL_IN, 37 XTAL_OUT/EXT_CLK, 38 AVDD10 (power), 39 RSET, 40 AVDD33 (power), 41 E_Pad

## FE1_1s_SSOP28_0
designator U?
pins: 1 AVDD (power), 2 DM2, 3 DP2, 4 RREF, 5 AVDD (power), 6 X1, 7 X2, 8 DM3, 9 DP3, 10 AVDD (power), 11 DM4, 12 DP4, 13 REST#, 14 TEST, 15 GND, 16 DVDD, 17 PSELF, 18 PGANG, 19 OVCUR2#, 20 PWREN2, 21 OVCUR1#, 22 PWREN1, 23 V5, 24 V33, 25 DM0, 26 DP0, 27 DMI, 28 DPI

## FE1_1s_SSOP28_1
designator U?
pins: 1 AVDD (power), 2 DM2, 3 DP2, 4 RREF, 5 AVDD (power), 6 X1, 7 X2, 8 DM3, 9 DP3, 10 AVDD (power), 11 DM4, 12 DP4, 13 REST#, 14 TEST, 15 GND, 16 DVDD, 17 PSELF, 18 PGANG, 19 OVCUR2#, 20 PWREN2, 21 OVCUR1#, 22 PWREN1, 23 V5, 24 V33, 25 DM0, 26 DP0, 27 DMI, 28 DPI

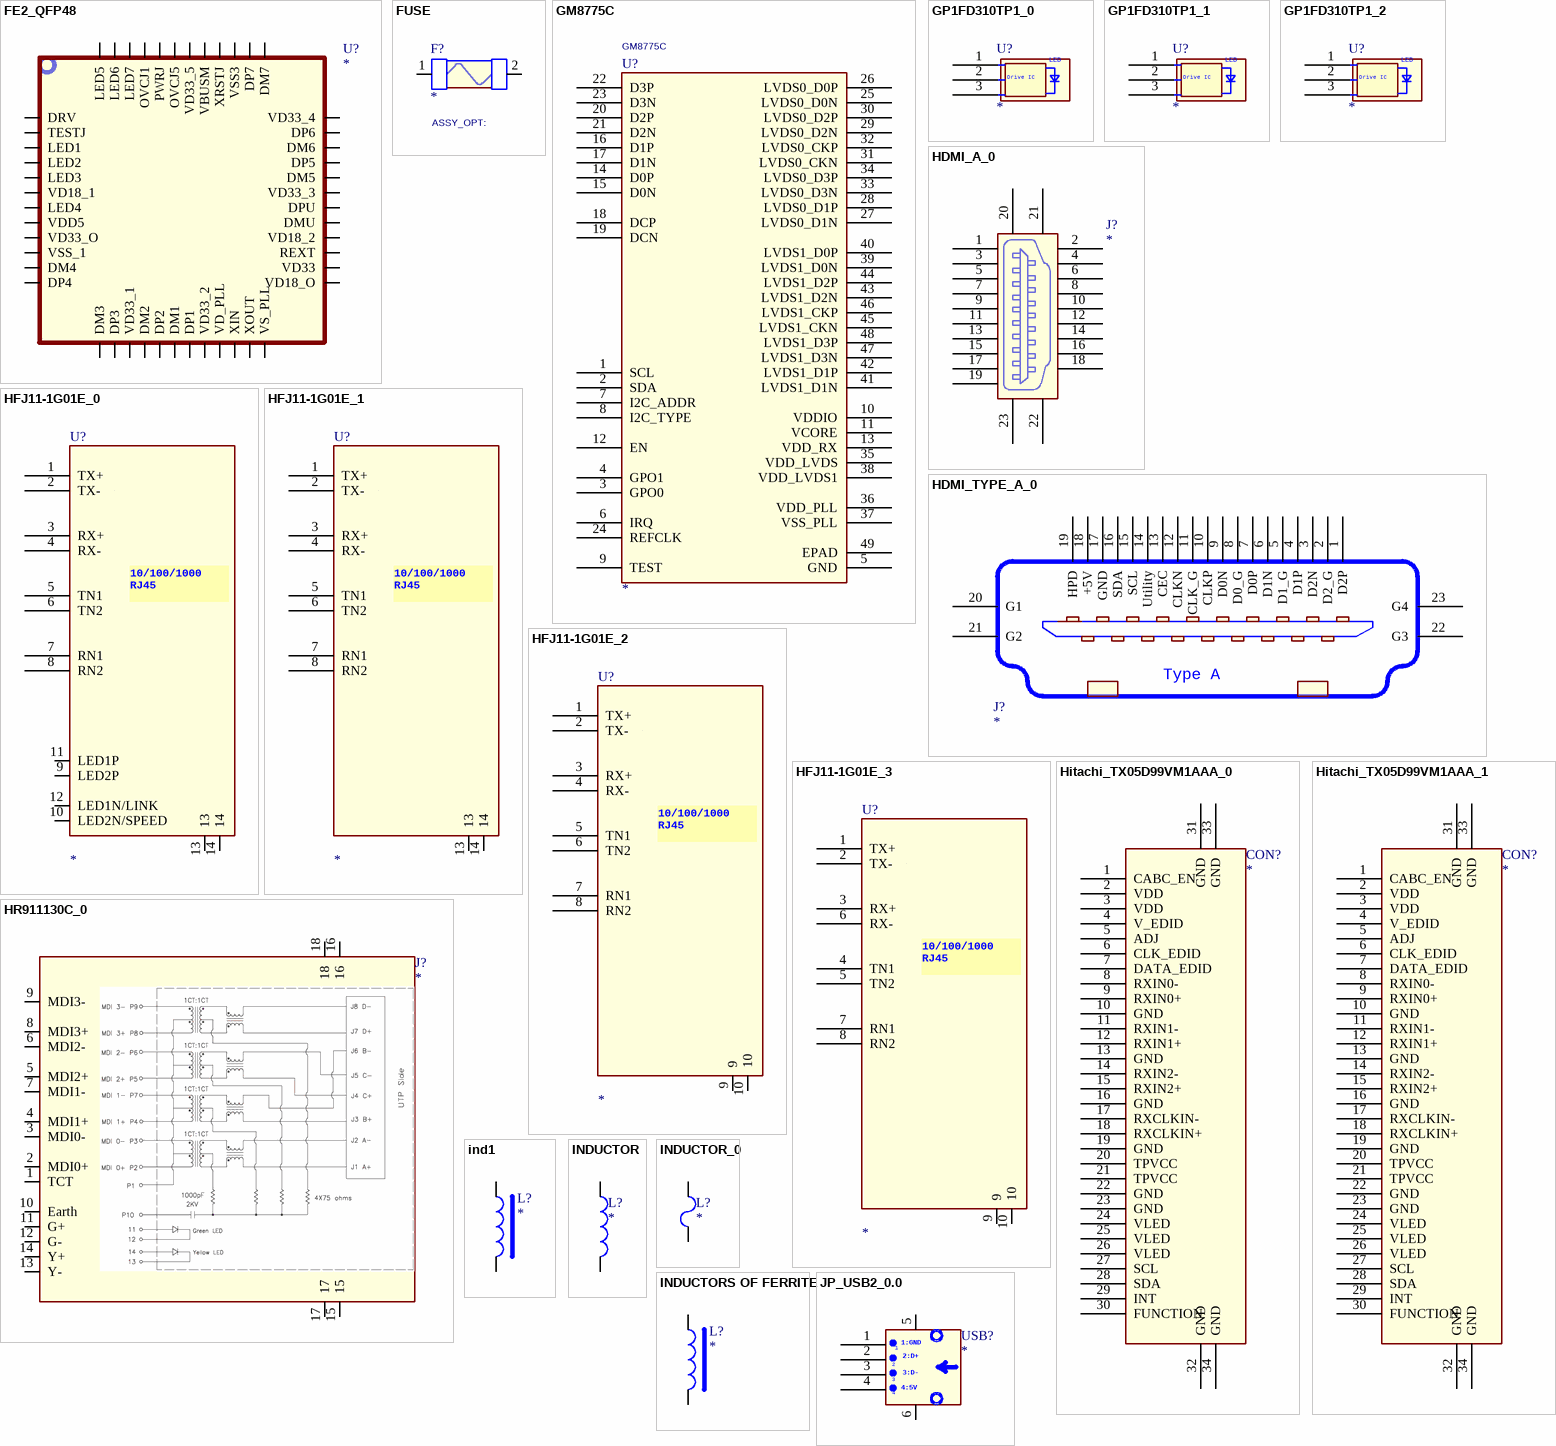
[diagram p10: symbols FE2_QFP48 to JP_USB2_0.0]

## FE2_QFP48
designator U?
pins: 1 DRV, 2 TESTJ, 3 LED1, 4 LED2, 5 LED3, 6 VD18_1, 7 LED4, 8 VDD5, 9 VD33_O, 10 VSS_1, 11 DM4, 12 DP4, 13 DM3, 14 DP3, 15 VD33_1, 16 DM2, 17 DP2, 18 DM1, 19 DP1, 20 VD33_2, 21 VD_PLL, 22 XIN, 23 XOUT, 24 VS_PLL, 25 VD18_O, 26 VD33, 27 REXT, 28 VD18_2, 29 DMU, 30 DPU, 31 VD33_3, 32 DM5, 33 DP5, 34 DM6, 35 DP6, 36 VD33_4, 37 DM7, 38 DP7, 39 VSS3, 40 XRSTJ, 41 VBUSM, 42 VD33_5, 43 OVCJ5, 44 PWRJ, 45 OVCJ1, 46 LED7, 47 LED6, 48 LED5

## FUSE
designator F?
CLASS: DISCRETE
pins: 1, 2

## GM8775C
designator U?  VAL: GM8775C
FAB: AD; DEV: SO16; REF: 3
pins: 1 SCL, 2 SDA, 3 GPO0, 4 GPO1, 5 GND, 6 IRQ, 7 I2C_ADDR, 8 I2C_TYPE, 9 TEST, 10 VDDIO, 11 VCORE, 12 EN, 13 VDD_RX, 14 D0P, 15 D0N, 16 D1P, 17 D1N, 18 DCP, 19 DCN, 20 D2P, 21 D2N, 22 D3P, 23 D3N, 24 REFCLK, 25 LVDS0_D0N, 26 LVDS0_D0P, 27 LVDS0_D1N, 28 LVDS0_D1P, 29 LVDS0_D2N, 30 LVDS0_D2P, 31 LVDS0_CKN, 32 LVDS0_CKP, 33 LVDS0_D3N, 34 LVDS0_D3P, 35 VDD_LVDS, 36 VDD_PLL, 37 VSS_PLL, 38 VDD_LVDS1, 39 LVDS1_D0N, 40 LVDS1_D0P, 41 LVDS1_D1N, 42 LVDS1_D1P, 43 LVDS1_D2N, 44 LVDS1_D2P, 45 LVDS1_CKN, 46 LVDS1_CKP, 47 LVDS1_D3N, 48 LVDS1_D3P, 49 EPAD

## GP1FD310TP1_0
designator U?
pins: 1 GND, 2 Vcc, 3 VIN

## GP1FD310TP1_1
designator U?
pins: 1 GND, 2 Vcc, 3 VIN

## GP1FD310TP1_2
designator U?
pins: 1 GND, 2 Vcc, 3 VIN

## HDMI_A_0
designator J?
pins: 1 $PIN0, 2, 3, 4, 5, 6, 7, 8, 9, 10, 11, 12, 13, 14, 15, 16, 17, 18, 19, 20, 21, 22, 23

## HDMI_TYPE_A_0
designator J?
pins: 1 D2P, 2 D2_G, 3 D2N, 4 D1P, 5 D1_G, 6 D1N, 7 D0P, 8 D0_G, 9 D0N, 10 CLKP, 11 CLK_G, 12 CLKN, 13 CEC, 14 Utility, 15 SCL, 16 SDA, 17 GND, 18 +5V, 19 HPD, 20 G1, 21 G2, 22 G3, 23 G4

## HFJ11-1G01E_0
designator U?
pins: 1 TX+, 2 TX-, 3 RX+, 4 RX-, 5 TN1, 6 TN2, 7 RN1, 8 RN2, 9 LED2P, 10 LED2N/SPEED, 11 LED1P, 12 LED1N/LINK, 13, 14

## HFJ11-1G01E_1
designator U?
pins: 1 TX+, 2 TX-, 3 RX+, 4 RX-, 5 TN1, 6 TN2, 7 RN1, 8 RN2, 13, 14

## HFJ11-1G01E_2
designator U?
pins: 1 TX+, 2 TX-, 3 RX+, 4 RX-, 5 TN1, 6 TN2, 7 RN1, 8 RN2, 9, 10

## HFJ11-1G01E_3
designator U?
pins: 1 TX+, 2 TX-, 3 RX+, 4 TN1, 5 TN2, 6 RX-, 7 RN1, 8 RN2, 9, 10

## Hitachi_TX05D99VM1AAA_0
designator CON?
pins: 1 CABC_EN, 2 VDD, 3 VDD, 4 V_EDID, 5 ADJ, 6 CLK_EDID, 7 DATA_EDID, 8 RXIN0-, 9 RXIN0+, 10 GND, 11 RXIN1-, 12 RXIN1+, 13 GND, 14 RXIN2-, 15 RXIN2+, 16 GND, 17 RXCLKIN-, 18 RXCLKIN+, 19 GND, 20 TPVCC, 21 TPVCC, 22 GND, 23 GND, 24 VLED, 25 VLED, 26 VLED, 27 SCL, 28 SDA, 29 INT, 30 FUNCTION, 31 GND, 32 GND, 33 GND, 34 GND

## Hitachi_TX05D99VM1AAA_1
designator CON?
pins: 1 CABC_EN, 2 VDD, 3 VDD, 4 V_EDID, 5 ADJ, 6 CLK_EDID, 7 DATA_EDID, 8 RXIN0-, 9 RXIN0+, 10 GND, 11 RXIN1-, 12 RXIN1+, 13 GND, 14 RXIN2-, 15 RXIN2+, 16 GND, 17 RXCLKIN-, 18 RXCLKIN+, 19 GND, 20 TPVCC, 21 TPVCC, 22 GND, 23 GND, 24 VLED, 25 VLED, 26 VLED, 27 SCL, 28 SDA, 29 INT, 30 FUNCTION, 31 GND, 32 GND, 33 GND, 34 GND

## HR911130C_0
designator J?
VAL: J00-0061; DESIG: 10/100 base TX LXT971A; BOI: RJ45; FAB: PULSE; DEV: CON_PULSE_J00-61
footprint RJ45_PULSE
pins: 1 TCT, 2 MDI0+, 3 MDI0-, 4 MDI1+, 5 MDI2+, 6 MDI2-, 7 MDI1-, 8 MDI3+, 9 MDI3-, 10 Earth, 11 G+, 12 G-, 13 Y-, 14 Y+, 15, 16, 17, 18

## ind1
designator L?
pins: 1, 2

## INDUCTOR
designator L?
pins: 1, 2

## INDUCTOR_0
designator L?
pins: 1, 2

## INDUCTORS OF FERRITE
designator L?
pins: 1, 2

## JP_USB2_0.0
designator USB?
footprint USB20
pins: 1, 2, 3, 4, 5, 6

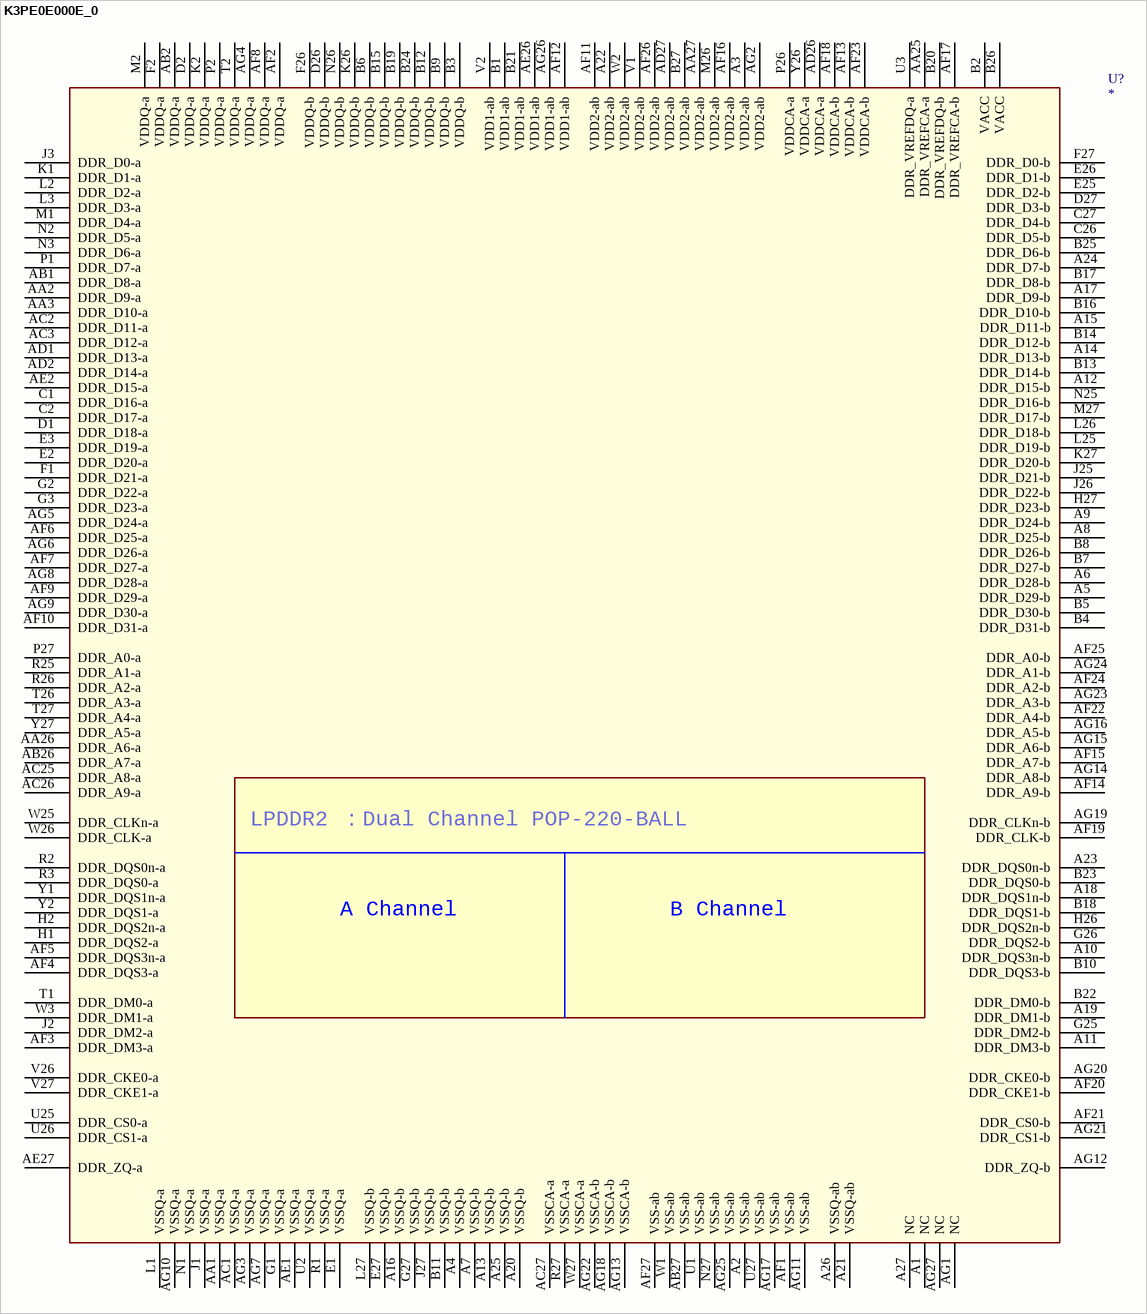
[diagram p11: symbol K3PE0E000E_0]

## K3PE0E000E_0
designator U?
footprint FBGA220-14X14
pins: A1 NC, A2 VSS-ab, A3 VDD2-ab, A4 VSSQ-b, A5 DDR_D29-b, A6 DDR_D28-b, A7 VSSQ-b, A8 DDR_D25-b, A9 DDR_D24-b, A10 DDR_DQS3n-b, A11 DDR_DM3-b, A12 DDR_D15-b, A13 VSSQ-b, A14 DDR_D13-b, A15 DDR_D11-b, A16 VSSQ-b, A17 DDR_D9-b, A18 DDR_DQS1n-b, A19 DDR_DM1-b, A20 VSSQ-b, A21 VSSQ-ab, A22 VDD2-ab, A23 DDR_DQS0n-b, A24 DDR_D7-b, A25 VSSQ-b, A26 VSSQ-ab, A27 NC, AA1 VSSQ-a, AA2 DDR_D9-a, AA3 DDR_D10-a, AA25 DDR_VREFCA-a, AA26 DDR_A6-a, AA27 VDD2-ab, AB1 DDR_D8-a, AB2 VDDQ-a, AB26 DDR_A7-a, AB27 VSS-ab, AC1 VSSQ-a, AC2 DDR_D11-a, AC3 DDR_D12-a, AC25 DDR_A8-a, AC26 DDR_A9-a, AC27 VSSCA-a, AD1 DDR_D13-a, AD2 DDR_D14-a, AD26 VDDCA-a, AD27 VDD2-ab, AE1 VSSQ-a, AE2 DDR_D15-a, AE26 VDD1-ab, AE27 DDR_ZQ-a, AF1 VSS-ab, AF2 VDDQ-a, AF3 DDR_DM3-a, AF4 DDR_DQS3-a, AF5 DDR_DQS3n-a, AF6 DDR_D25-a, AF7 DDR_D27-a, AF8 VDDQ-a, AF9 DDR_D29-a, AF10 DDR_D31-a, AF11 VDD2-ab, AF12 VDD1-ab, AF13 VDDCA-b, AF14 DDR_A9-b, AF15 DDR_A7-b, AF16 VDD2-ab, AF17 DDR_VREFCA-b, AF18 VDDCA-b, AF19 DDR_CLK-b, AF20 DDR_CKE1-b, AF21 DDR_CS0-b, AF22 DDR_A4-b, AF23 VDDCA-b, AF24 DDR_A2-b, AF25 DDR_A0-b, AF26 VDD2-ab, AF27 VSS-ab, AG1 NC, AG2 VDD2-ab, AG3 VSSQ-a, AG4 VDDQ-a, AG5 DDR_D24-a, AG6 DDR_D26-a, AG7 VSSQ-a, AG8 DDR_D28-a, AG9 DDR_D30-a, AG10 VSSQ-a, AG11 VSS-ab, AG12 DDR_ZQ-b, AG13 VSSCA-b, AG14 DDR_A8-b, AG15 DDR_A6-b, AG16 DDR_A5-b, AG17 VSS-ab, AG18 VSSCA-b, AG19 DDR_CLKn-b, AG20 DDR_CKE0-b, AG21 DDR_CS1-b, AG22 VSSCA-b, AG23 DDR_A3-b, AG24 DDR_A1-b, AG25 VSS-ab, AG26 VDD1-ab, AG27 NC, B1 VDD1-ab, B2 VACC, B3 VDDQ-b, B4 DDR_D31-b, B5 DDR_D30-b, B6 VDDQ-b, B7 DDR_D27-b, B8 DDR_D26-b, B9 VDDQ-b, B10 DDR_DQS3-b, B11 VSSQ-b, B12 VDDQ-b, B13 DDR_D14-b, B14 DDR_D12-b, B15 VDDQ-b, B16 DDR_D10-b, B17 DDR_D8-b, B18 DDR_DQS1-b, B19 VDDQ-b, B20 DDR_VREFDQ-b, B21 VDD1-ab, B22 DDR_DM0-b, B23 DDR_DQS0-b, B24 VDDQ-b, B25 DDR_D6-b, B26 VACC, B27 VDD2-ab, C1 DDR_D16-a, C2 DDR_D17-a, C26 DDR_D5-b, C27 DDR_D4-b, D1 DDR_D18-a, D2 VDDQ-a, D26 VDDQ-b, D27 DDR_D3-b, E1 VSSQ-a, E2 DDR_D20-a, E3 DDR_D19-a, E25 DDR_D2-b, E26 DDR_D1-b, E27 VSSQ-b, F1 DDR_D21-a, F2 VDDQ-a, F26 VDDQ-b, F27 DDR_D0-b, G1 VSSQ-a, G2 DDR_D22-a, G3 DDR_D23-a, G25 DDR_DM2-b, G26 DDR_DQS2-b, G27 VSSQ-b, H1 DDR_DQS2-a, H2 DDR_DQS2n-a, H26 DDR_DQS2n-b, H27 DDR_D23-b, J1 VSSQ-a, J2 DDR_DM2-a, J3 DDR_D0-a, J25 DDR_D21-b, J26 DDR_D22-b, J27 VSSQ-b, K1 DDR_D1-a, K2 VDDQ-a, K26 VDDQ-b, K27 DDR_D20-b, L1 VSSQ-a, L2 DDR_D2-a, L3 DDR_D3-a, L25 DDR_D19-b, L26 DDR_D18-b, L27 VSSQ-b, M1 DDR_D4-a, M2 VDDQ-a, M26 VDD2-ab, M27 DDR_D17-b, N1 VSSQ-a, N2 DDR_D5-a, N3 DDR_D6-a, N25 DDR_D16-b, N26 VDDQ-b, N27 VSS-ab, P1 DDR_D7-a, P2 VDDQ-a, P26 VDDCA-a, P27 DDR_A0-a, R1 VSSQ-a, R2 DDR_DQS0n-a, R3 DDR_DQS0-a, R25 DDR_A1-a, R26 DDR_A2-a, R27 VSSCA-a, T1 DDR_DM0-a, T2 VDDQ-a, T26 DDR_A3-a, T27 DDR_A4-a, U1 VSS-ab, U2 VSSQ-a, U3 DDR_VREFDQ-a, U25 DDR_CS0-a, U26 DDR_CS1-a, U27 VSS-ab, V1 VDD2-ab, V2 VDD1-ab, V26 DDR_CKE0-a, V27 DDR_CKE1-a, W1 VSS-ab, W2 VDD2-ab, W3 DDR_DM1-a, W25 DDR_CLKn-a, W26 DDR_CLK-a, W27 VSSCA-a, Y1 DDR_DQS1n-a, Y2 DDR_DQS1-a, Y26 VDDCA-a, Y27 DDR_A5-a

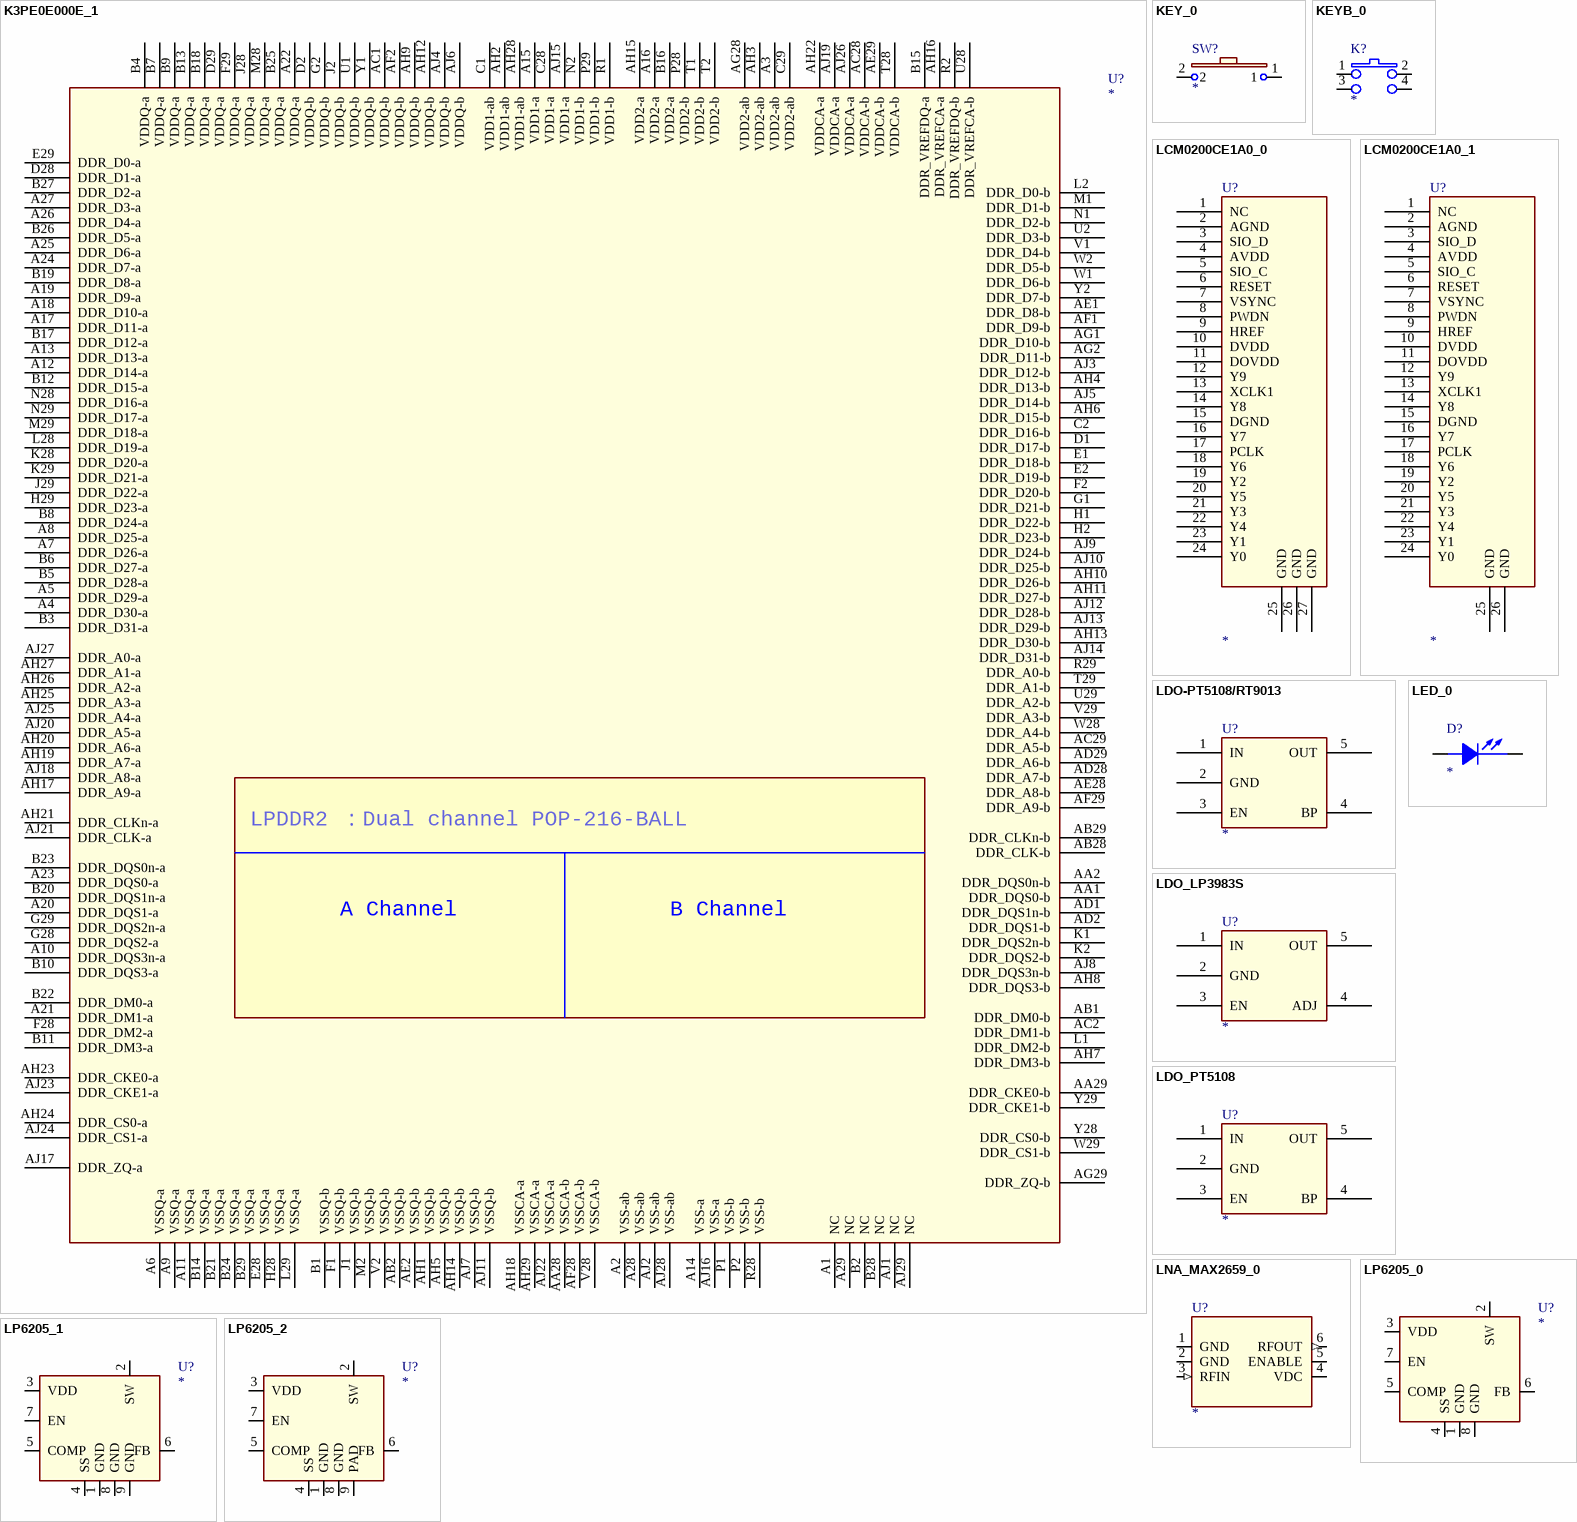
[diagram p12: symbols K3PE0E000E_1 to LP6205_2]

## K3PE0E000E_1
designator U?
footprint FBGA220-14X14
pins: A1 NC, A2 VSS-ab, A3 VDD2-ab, A4 DDR_D30-a, A5 DDR_D29-a, A6 VSSQ-a, A7 DDR_D26-a, A8 DDR_D25-a, A9 VSSQ-a, A10 DDR_DQS3n-a, A11 VSSQ-a, A12 DDR_D14-a, A13 DDR_D13-a, A14 VSS-a, A15 VDD1-a, A16 VDD2-a, A17 DDR_D11-a, A18 DDR_D10-a, A19 DDR_D9-a, A20 DDR_DQS1-a, A21 DDR_DM1-a, A22 VDDQ-a, A23 DDR_DQS0-a, A24 DDR_D7-a, A25 DDR_D6-a, A26 DDR_D4-a, A27 DDR_D3-a, A28 VSS-ab, A29 NC, AA1 DDR_DQS0-b, AA2 DDR_DQS0n-b, AA28 VSSCA-b, AA29 DDR_CKE0-b, AB1 DDR_DM0-b, AB2 VSSQ-b, AB28 DDR_CLK-b, AB29 DDR_CLKn-b, AC1 VDDQ-b, AC2 DDR_DM1-b, AC28 VDDCA-b, AC29 DDR_A5-b, AD1 DDR_DQS1n-b, AD2 DDR_DQS1-b, AD28 DDR_A7-b, AD29 DDR_A6-b, AE1 DDR_D8-b, AE2 VSSQ-b, AE28 DDR_A8-b, AE29 VDDCA-b, AF1 DDR_D9-b, AF2 VDDQ-b, AF28 VSSCA-b, AF29 DDR_A9-b, AG1 DDR_D10-b, AG2 DDR_D11-b, AG28 VDD2-ab, AG29 DDR_ZQ-b, AH1 VSSQ-b, AH2 VDD1-ab, AH3 VDD2-ab, AH4 DDR_D13-b, AH5 VSSQ-b, AH6 DDR_D15-b, AH7 DDR_DM3-b, AH8 DDR_DQS3-b, AH9 VDDQ-b, AH10 DDR_D26-b, AH11 DDR_D27-b, AH12 VDDQ-b, AH13 DDR_D30-b, AH14 VSSQ-b, AH15 VDD2-a, AH16 DDR_VREFCA-a, AH17 DDR_A9-a, AH18 VSSCA-a, AH19 DDR_A7-a, AH20 DDR_A6-a, AH21 DDR_CLKn-a, AH22 VDDCA-a, AH23 DDR_CKE0-a, AH24 DDR_CS0-a, AH25 DDR_A3-a, AH26 DDR_A2-a, AH27 DDR_A1-a, AH28 VDD1-ab, AH29 VSSCA-a, AJ1 NC, AJ2 VSS-ab, AJ3 DDR_D12-b, AJ4 VDDQ-b, AJ5 DDR_D14-b, AJ6 VDDQ-b, AJ7 VSSQ-b, AJ8 DDR_DQS3n-b, AJ9 DDR_D24-b, AJ10 DDR_D25-b, AJ11 VSSQ-b, AJ12 DDR_D28-b, AJ13 DDR_D29-b, AJ14 DDR_D31-b, AJ15 VDD1-a, AJ16 VSS-a, AJ17 DDR_ZQ-a, AJ18 DDR_A8-a, AJ19 VDDCA-a, AJ20 DDR_A5-a, AJ21 DDR_CLK-a, AJ22 VSSCA-a, AJ23 DDR_CKE1-a, AJ24 DDR_CS1-a, AJ25 DDR_A4-a, AJ26 VDDCA-a, AJ27 DDR_A0-a, AJ28 VSS-ab, AJ29 NC, B1 VSSQ-b, B2 NC, B3 DDR_D31-a, B4 VDDQ-a, B5 DDR_D28-a, B6 DDR_D27-a, B7 VDDQ-a, B8 DDR_D24-a, B9 VDDQ-a, B10 DDR_DQS3-a, B11 DDR_DM3-a, B12 DDR_D15-a, B13 VDDQ-a, B14 VSSQ-a, B15 DDR_VREFDQ-a, B16 VDD2-a, B17 DDR_D12-a, B18 VDDQ-a, B19 DDR_D8-a, B20 DDR_DQS1n-a, B21 VSSQ-a, B22 DDR_DM0-a, B23 DDR_DQS0n-a, B24 VSSQ-a, B25 VDDQ-a, B26 DDR_D5-a, B27 DDR_D2-a, B28 NC, B29 VSSQ-a, C1 VDD1-ab, C2 DDR_D16-b, C28 VDD1-a, C29 VDD2-ab, D1 DDR_D17-b, D2 VDDQ-b, D28 DDR_D1-a, D29 VDDQ-a, E1 DDR_D18-b, E2 DDR_D19-b, E28 VSSQ-a, E29 DDR_D0-a, F1 VSSQ-b, F2 DDR_D20-b, F28 DDR_DM2-a, F29 VDDQ-a, G1 DDR_D21-b, G2 VDDQ-b, G28 DDR_DQS2-a, G29 DDR_DQS2n-a, H1 DDR_D22-b, H2 DDR_D23-b, H28 VSSQ-a, H29 DDR_D23-a, J1 VSSQ-b, J2 VDDQ-b, J28 VDDQ-a, J29 DDR_D22-a, K1 DDR_DQS2n-b, K2 DDR_DQS2-b, K28 DDR_D20-a, K29 DDR_D21-a, L1 DDR_DM2-b, L2 DDR_D0-b, L28 DDR_D19-a, L29 VSSQ-a, M1 DDR_D1-b, M2 VSSQ-b, M28 VDDQ-a, M29 DDR_D18-a, N1 DDR_D2-b, N2 VDD1-b, N28 DDR_D16-a, N29 DDR_D17-a, P1 VSS-b, P2 VSS-b, P28 VDD2-b, P29 VDD1-b, R1 VDD1-b, R2 DDR_VREFDQ-b, R28 VSS-b, R29 DDR_A0-b, T1 VDD2-b, T2 VDD2-b, T28 VDDCA-b, T29 DDR_A1-b, U1 VDDQ-b, U2 DDR_D3-b, U28 DDR_VREFCA-b, U29 DDR_A2-b, V1 DDR_D4-b, V2 VSSQ-b, V28 VSSCA-b, V29 DDR_A3-b, W1 DDR_D6-b, W2 DDR_D5-b, W28 DDR_A4-b, W29 DDR_CS1-b, Y1 VDDQ-b, Y2 DDR_D7-b, Y28 DDR_CS0-b, Y29 DDR_CKE1-b

## KEY_0
designator SW?
footprint YC-6615B
pins: 1, 2

## KEYB_0
designator K?
footprint KEYB
pins: 1, 2, 3, 4

## LCM0200CE1A0_0
designator U?
pins: 1 NC, 2 AGND, 3 SIO_D, 4 AVDD, 5 SIO_C, 6 RESET, 7 VSYNC, 8 PWDN, 9 HREF, 10 DVDD, 11 DOVDD, 12 Y9, 13 XCLK1, 14 Y8, 15 DGND, 16 Y7, 17 PCLK, 18 Y6, 19 Y2, 20 Y5, 21 Y3, 22 Y4, 23 Y1, 24 Y0, 25 GND, 26 GND, 27 GND

## LCM0200CE1A0_1
designator U?
pins: 1 NC, 2 AGND, 3 SIO_D, 4 AVDD, 5 SIO_C, 6 RESET, 7 VSYNC, 8 PWDN, 9 HREF, 10 DVDD, 11 DOVDD, 12 Y9, 13 XCLK1, 14 Y8, 15 DGND, 16 Y7, 17 PCLK, 18 Y6, 19 Y2, 20 Y5, 21 Y3, 22 Y4, 23 Y1, 24 Y0, 25 GND, 26 GND

## LDO-PT5108/RT9013
designator U?
pins: 1 IN, 2 GND, 3 EN, 4 BP, 5 OUT

## LDO_LP3983S
designator U?
pins: 1 IN, 2 GND, 3 EN, 4 ADJ, 5 OUT

## LDO_PT5108
designator U?
pins: 1 IN, 2 GND, 3 EN, 4 BP, 5 OUT

## LED_0
designator D?
pins: 1, 2

## LNA_MAX2659_0
designator U?
footprint P-TSLP-7-1
pins: 1 GND (power), 2 GND, 3 RFIN (in), 4 VDC (power), 5 ENABLE, 6 RFOUT (out)

## LP6205_0
designator U?
pins: 1 GND, 2 SW, 3 VDD, 4 SS, 5 COMP, 6 FB, 7 EN, 8 GND

## LP6205_1
designator U?
pins: 1 GND, 2 SW, 3 VDD, 4 SS, 5 COMP, 6 FB, 7 EN, 8 GND, 9 GND

## LP6205_2
designator U?
pins: 1 GND, 2 SW, 3 VDD, 4 SS, 5 COMP, 6 FB, 7 EN, 8 GND, 9 PAD

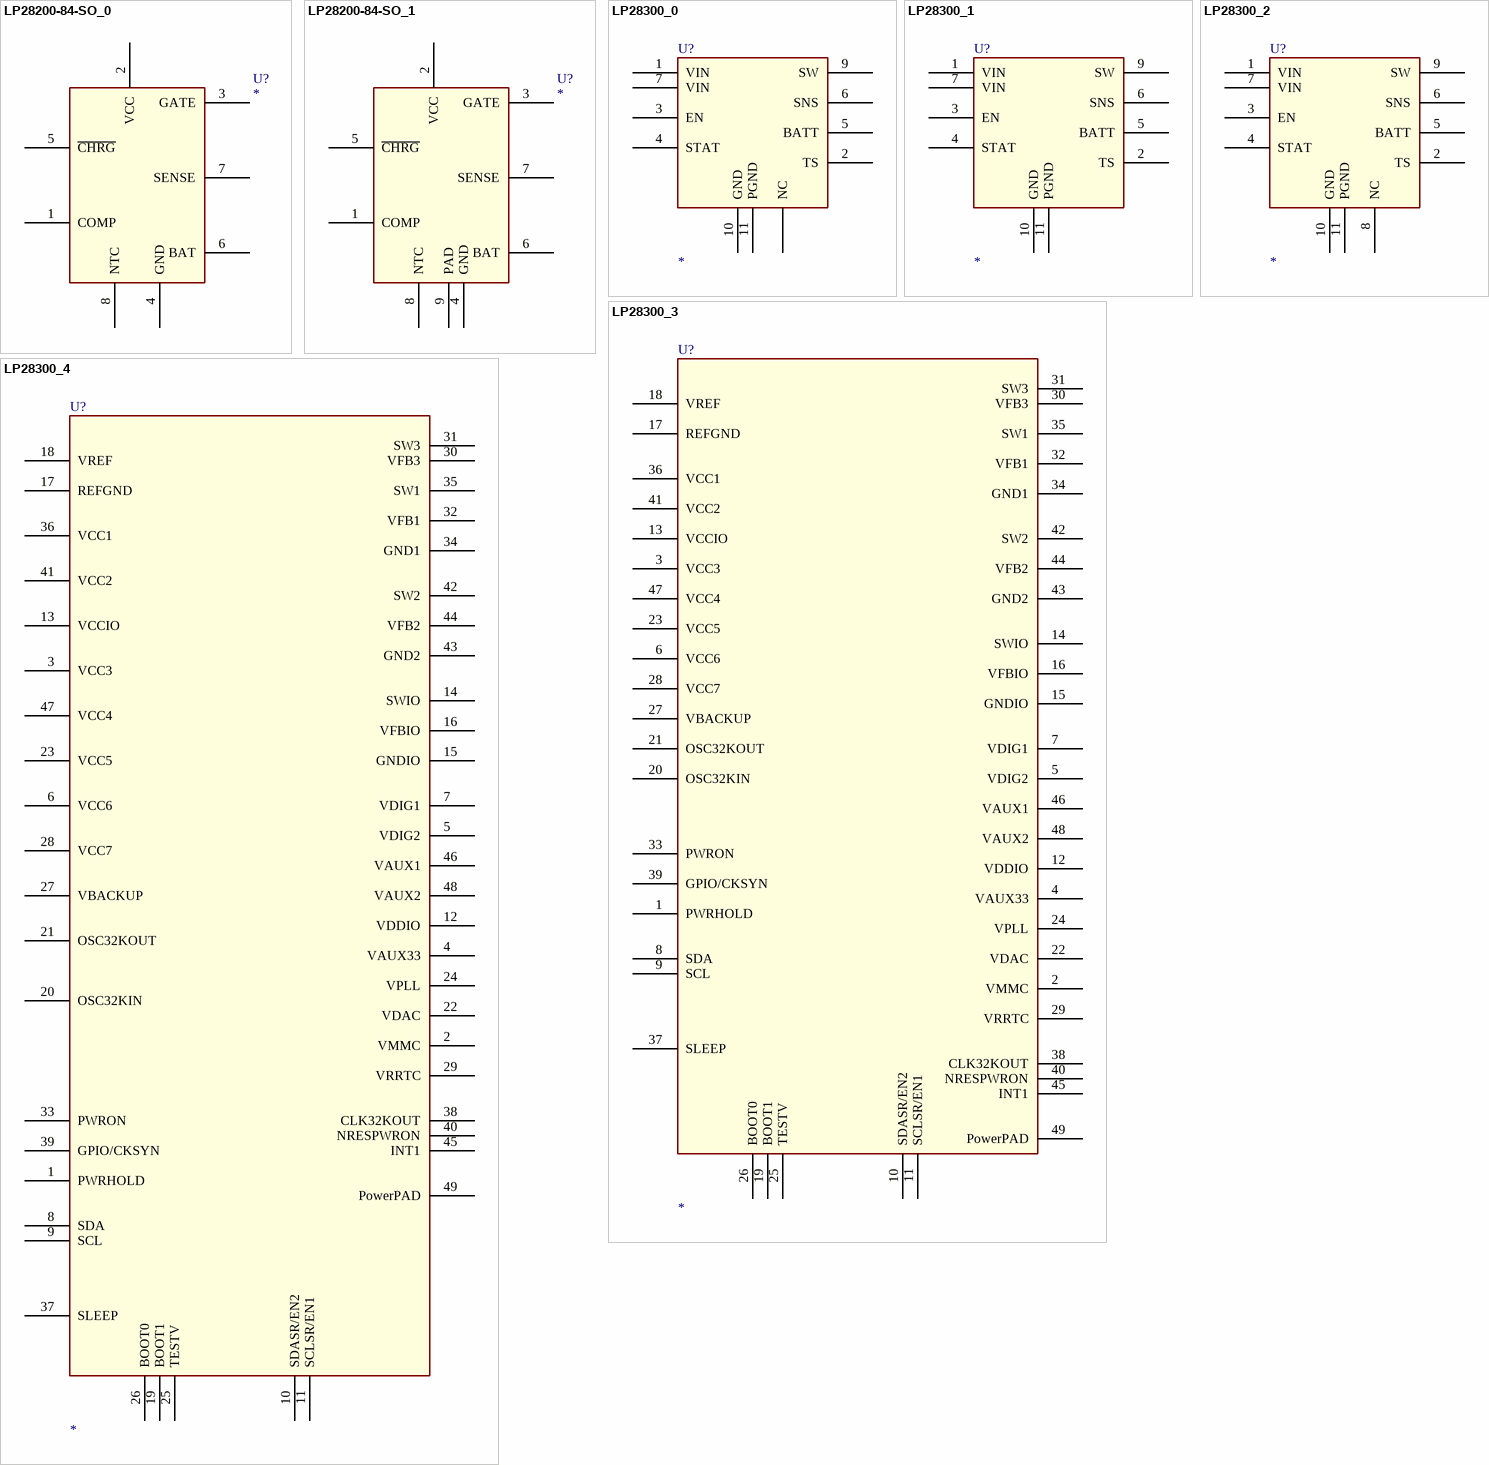
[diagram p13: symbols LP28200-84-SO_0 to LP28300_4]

## LP28200-84-SO_0
designator U?
footprint SOP8
pins: 1 COMP, 2 VCC, 3 GATE, 4 GND, 5 ~{CHRG}, 6 BAT, 7 SENSE, 8 NTC

## LP28200-84-SO_1
designator U?
footprint SOP8
pins: 1 COMP, 2 VCC, 3 GATE, 4 GND, 5 ~{CHRG}, 6 BAT, 7 SENSE, 8 NTC, 9 PAD

## LP28300_0
designator U?
footprint TDFN10
pins: 1 VIN, 2 TS, 3 EN, 4 STAT, 5 BATT, 6 SNS, 7 VIN, 9 SW, 10 GND, 11 PGND, NC

## LP28300_1
designator U?
footprint TDFN10
pins: 1 VIN, 2 TS, 3 EN, 4 STAT, 5 BATT, 6 SNS, 7 VIN, 9 SW, 10 GND, 11 PGND

## LP28300_2
designator U?
footprint TDFN10
pins: 1 VIN, 2 TS, 3 EN, 4 STAT, 5 BATT, 6 SNS, 7 VIN, 8 NC, 9 SW, 10 GND, 11 PGND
